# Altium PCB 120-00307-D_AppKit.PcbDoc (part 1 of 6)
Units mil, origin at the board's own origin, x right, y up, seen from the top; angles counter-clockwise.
Board outline 5150 x 3100 mil, 6 copper layers (L1, L2 (GND), L3-SIG, L4-SIG, L5 (PWR), L6), stack 61.956 mil thick; 413 components, 344 nets, 1685 pads, 1021 vias.
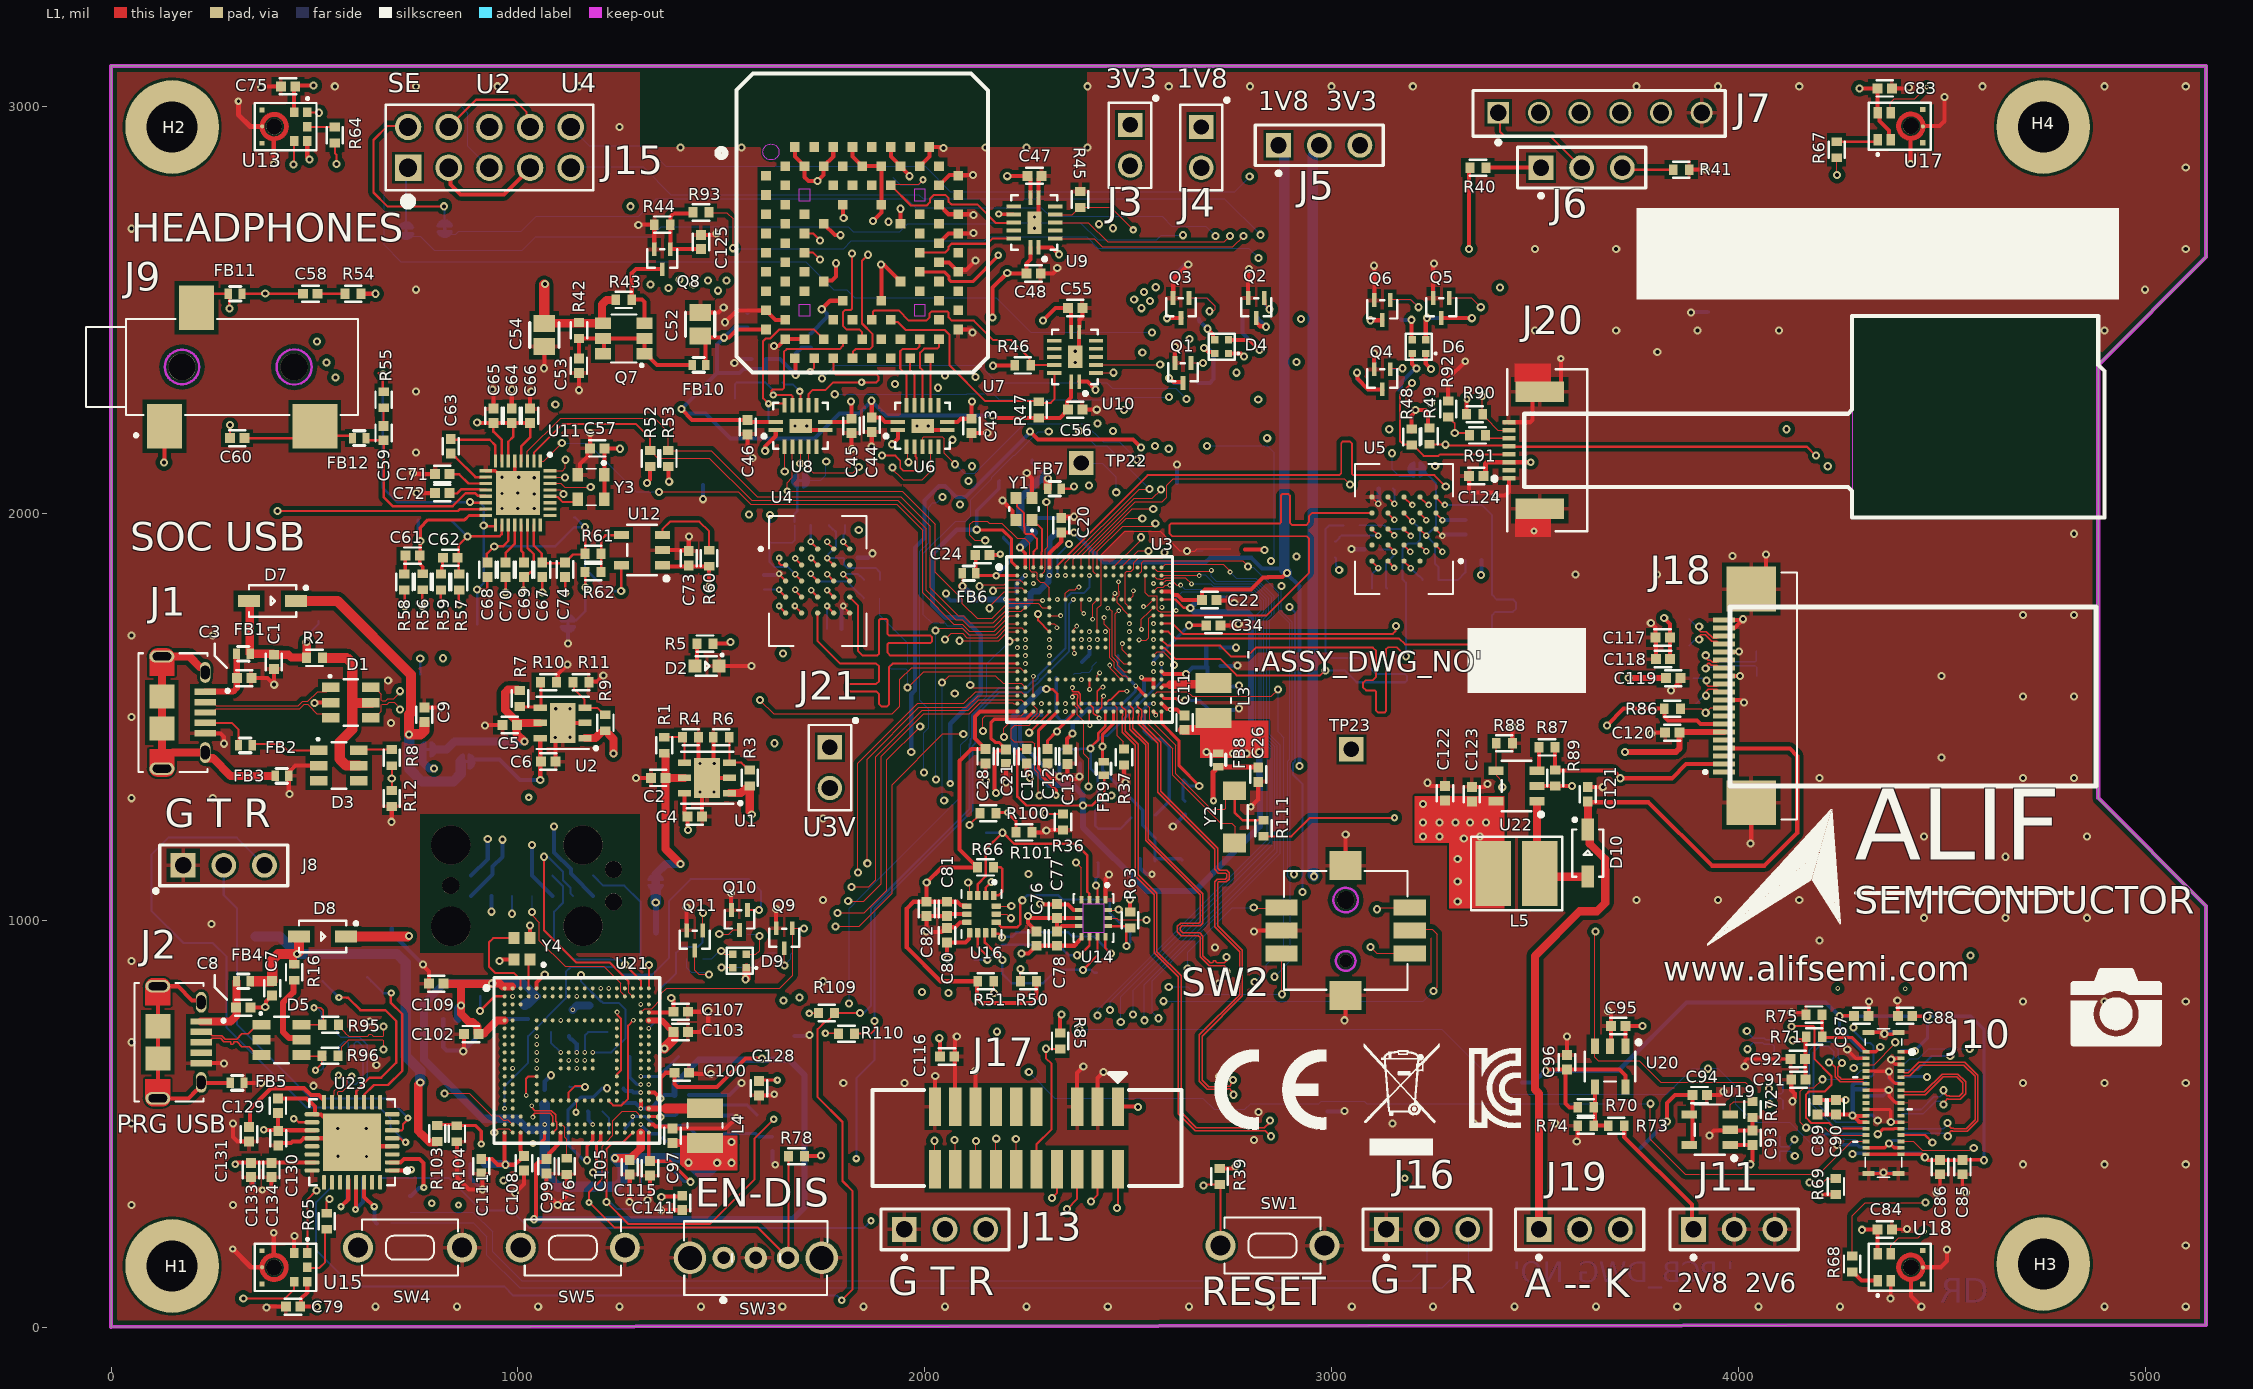
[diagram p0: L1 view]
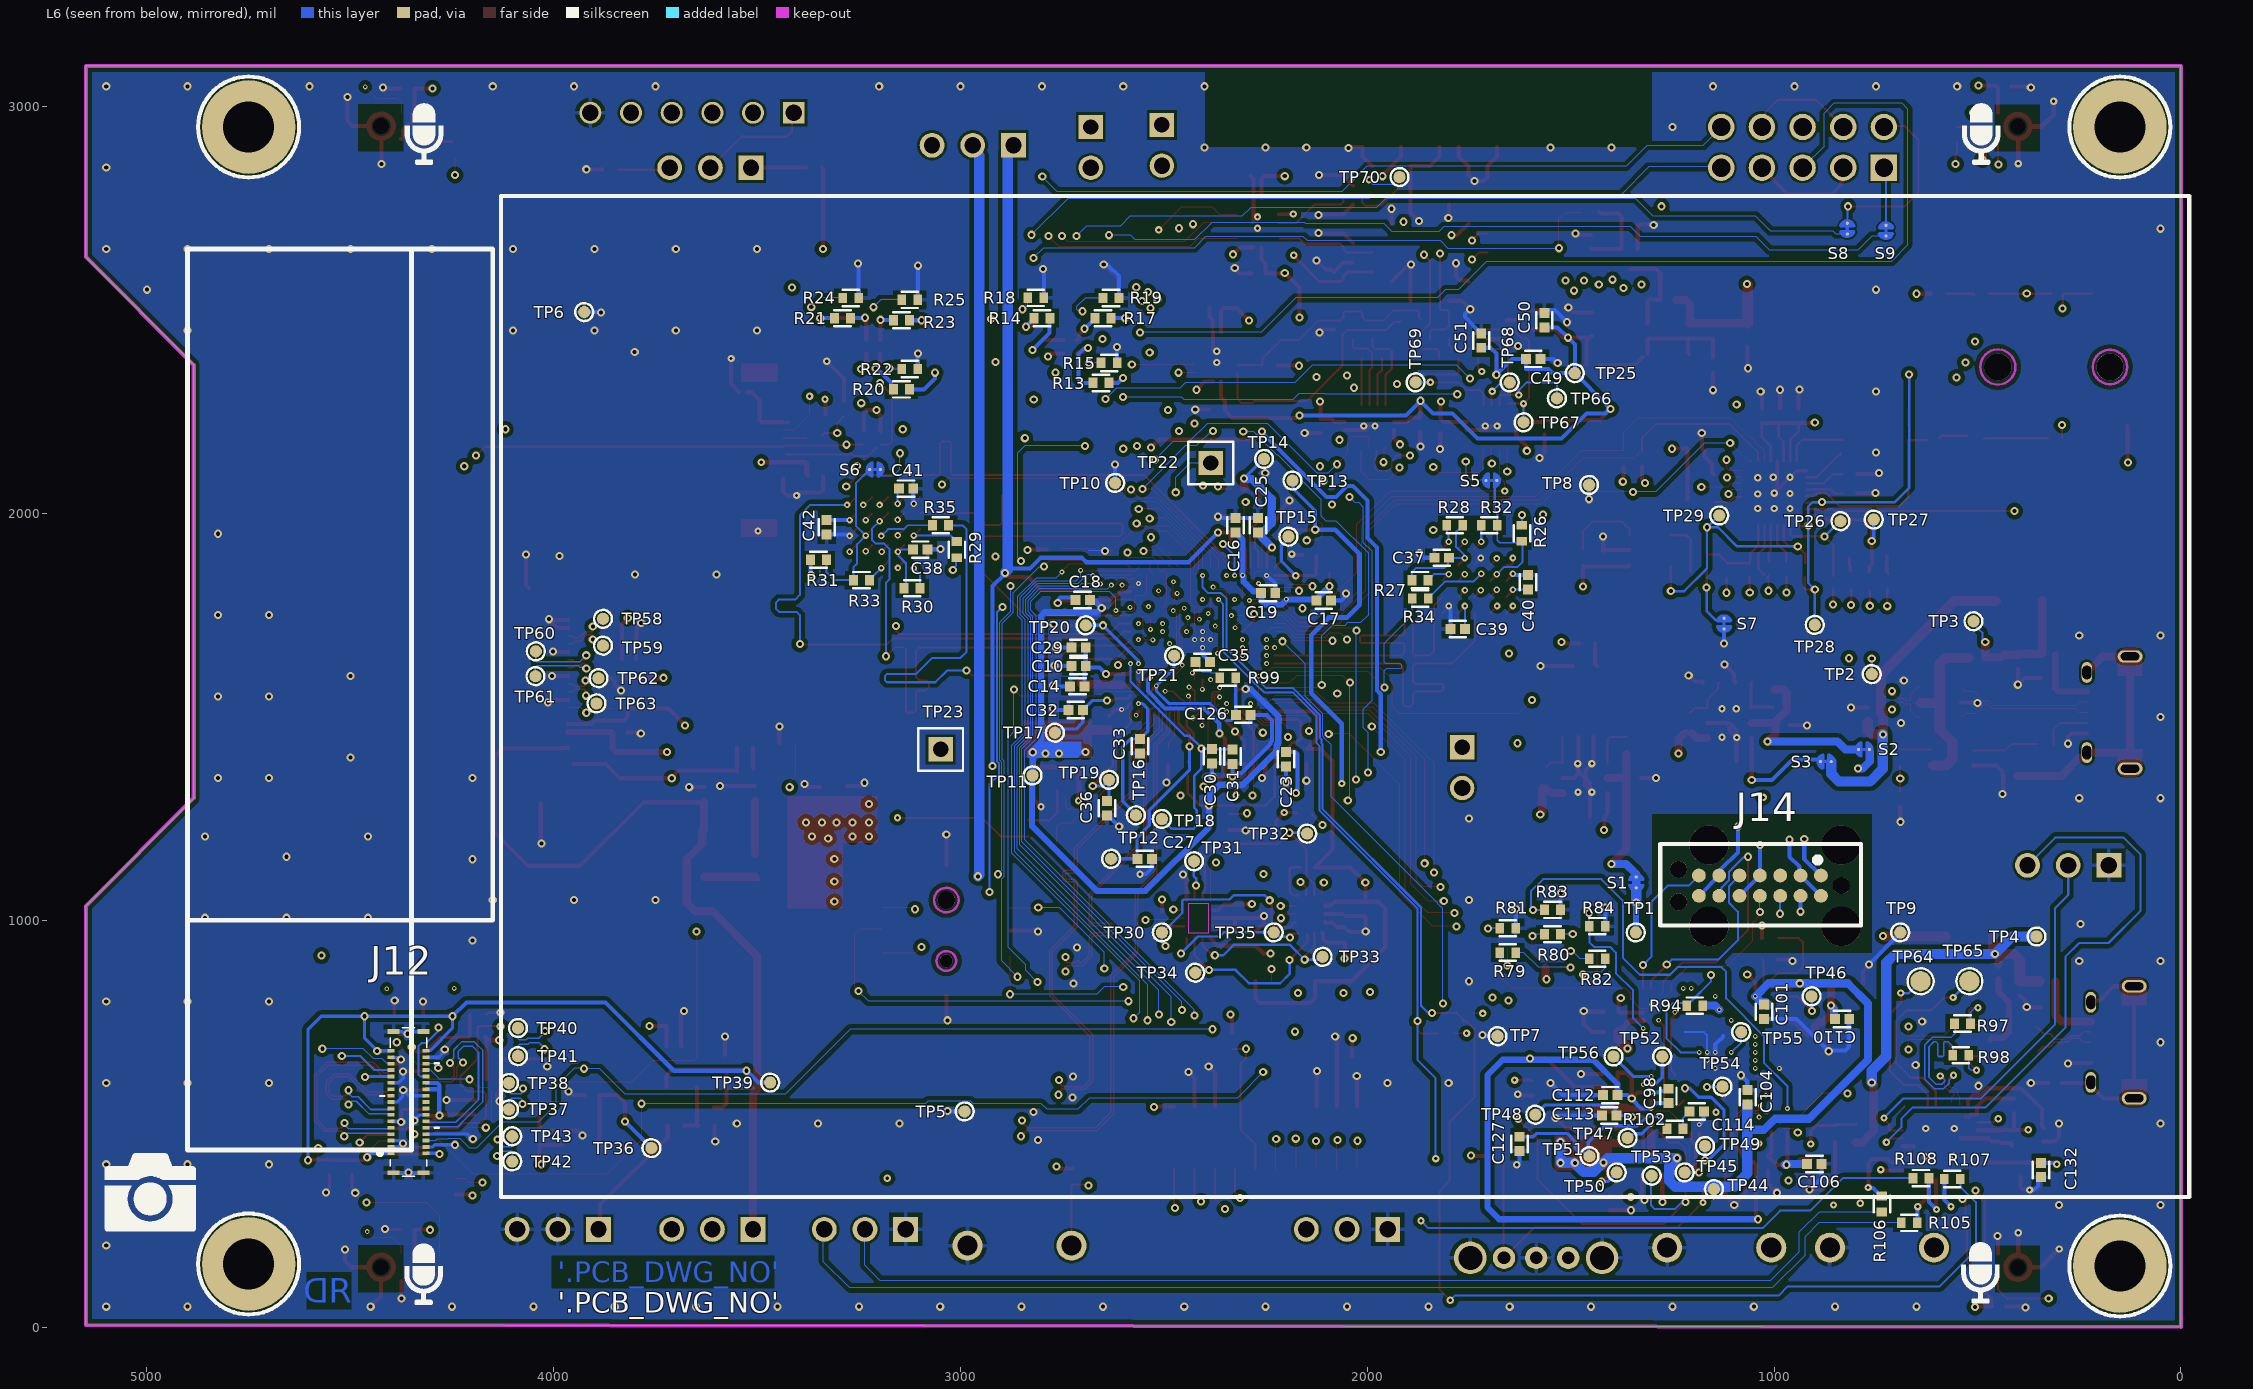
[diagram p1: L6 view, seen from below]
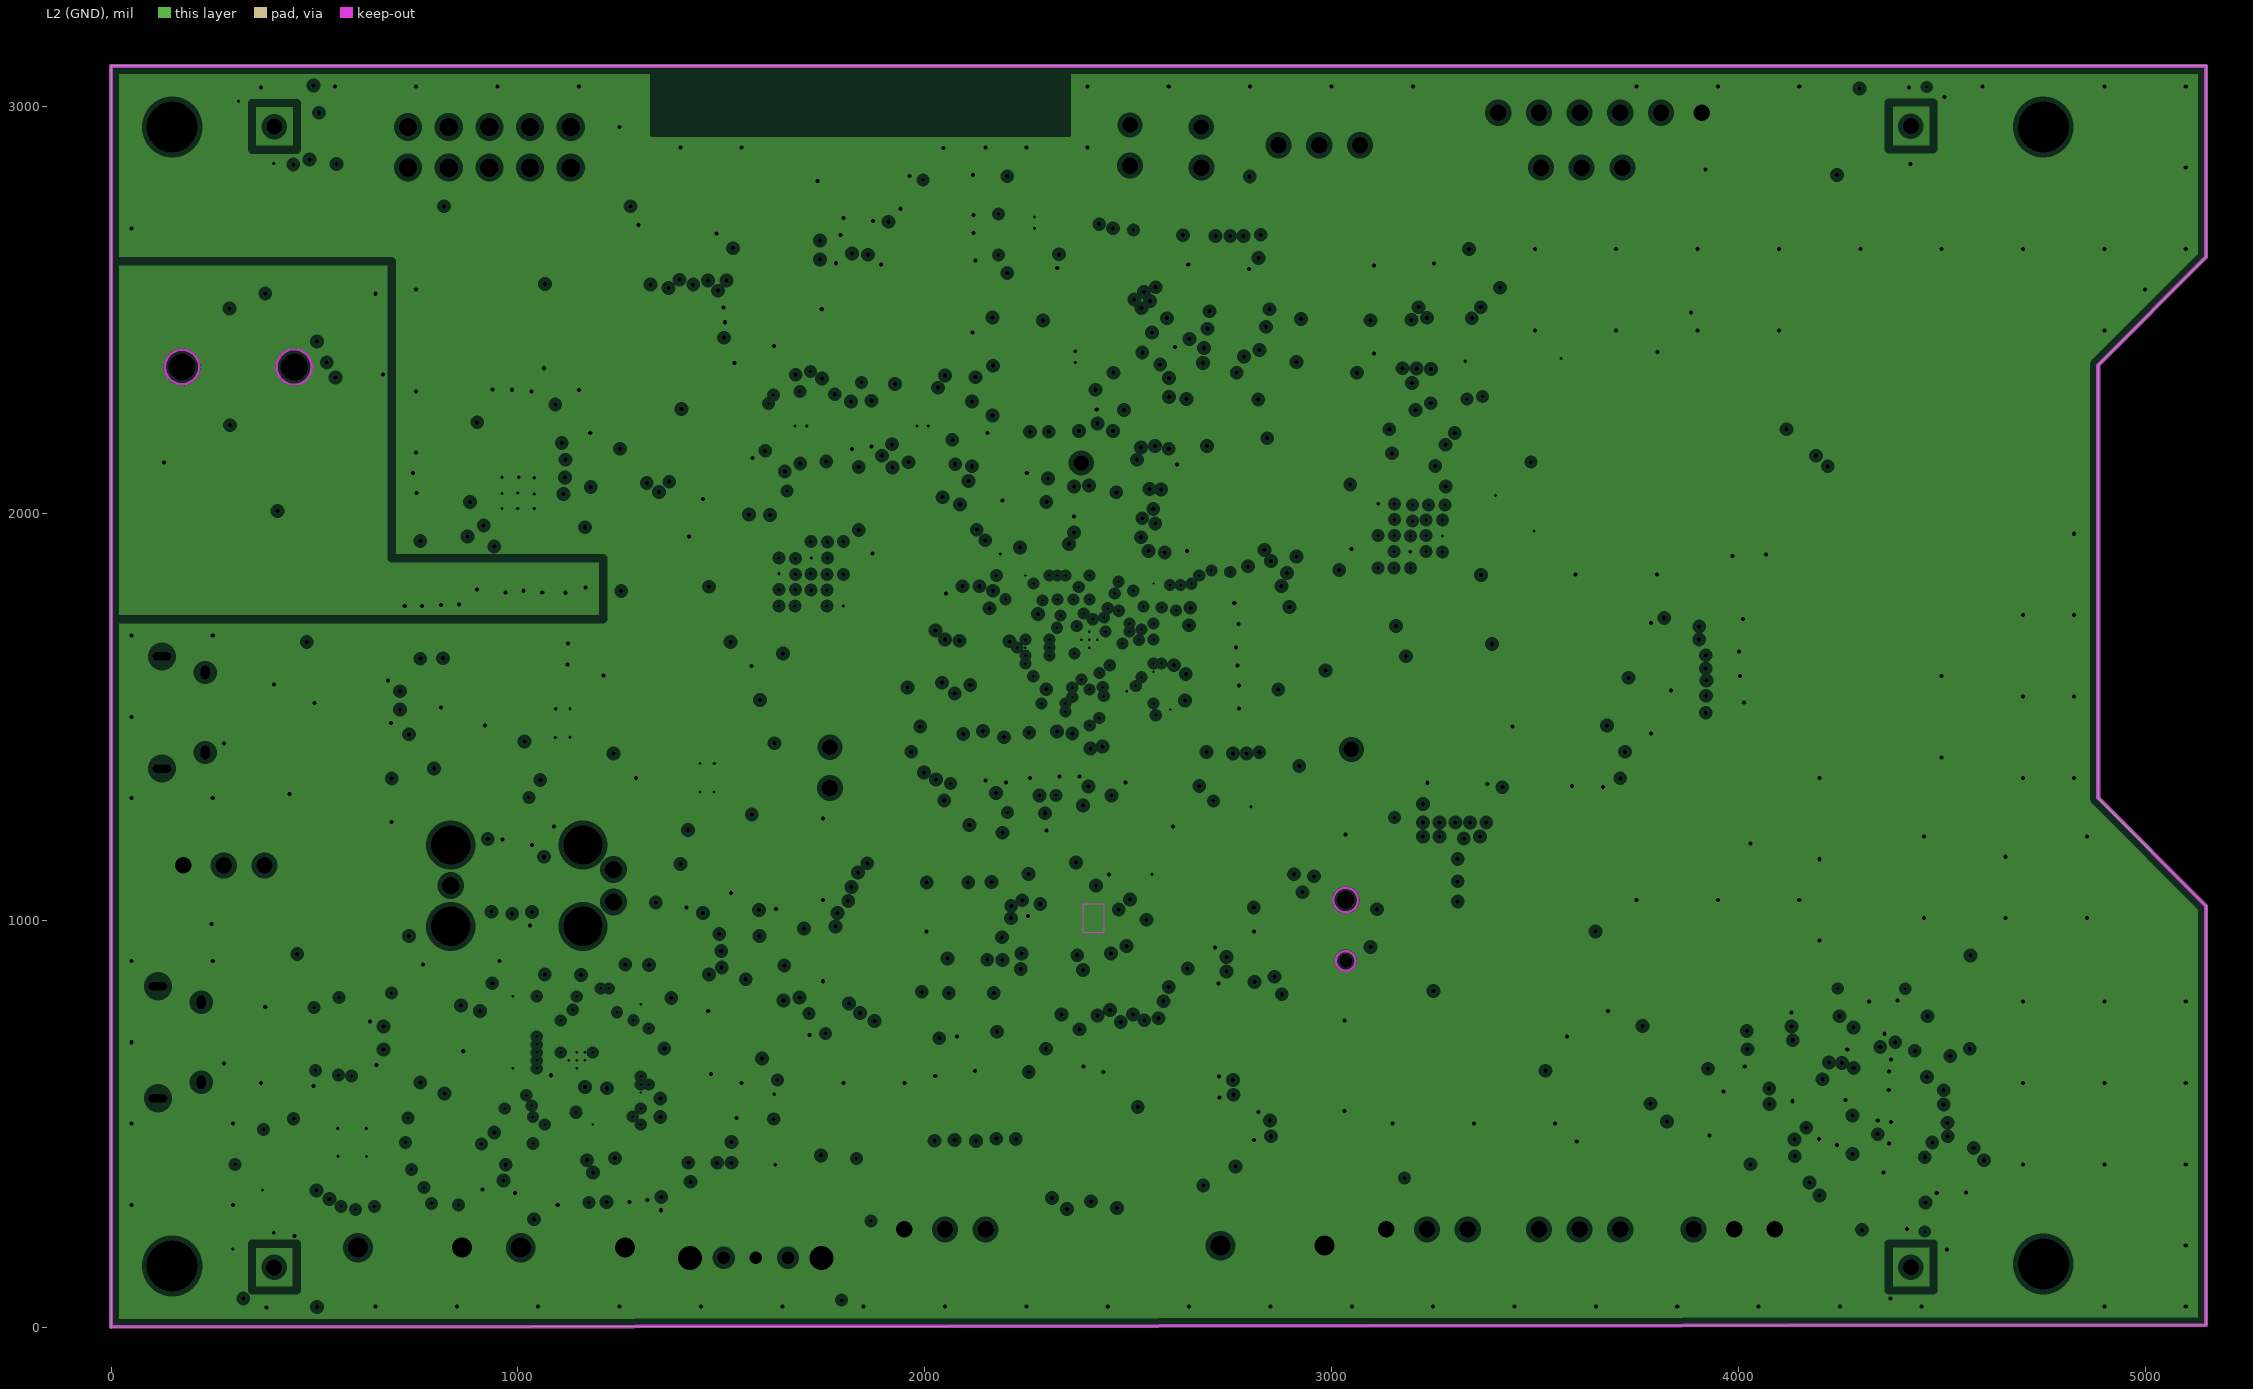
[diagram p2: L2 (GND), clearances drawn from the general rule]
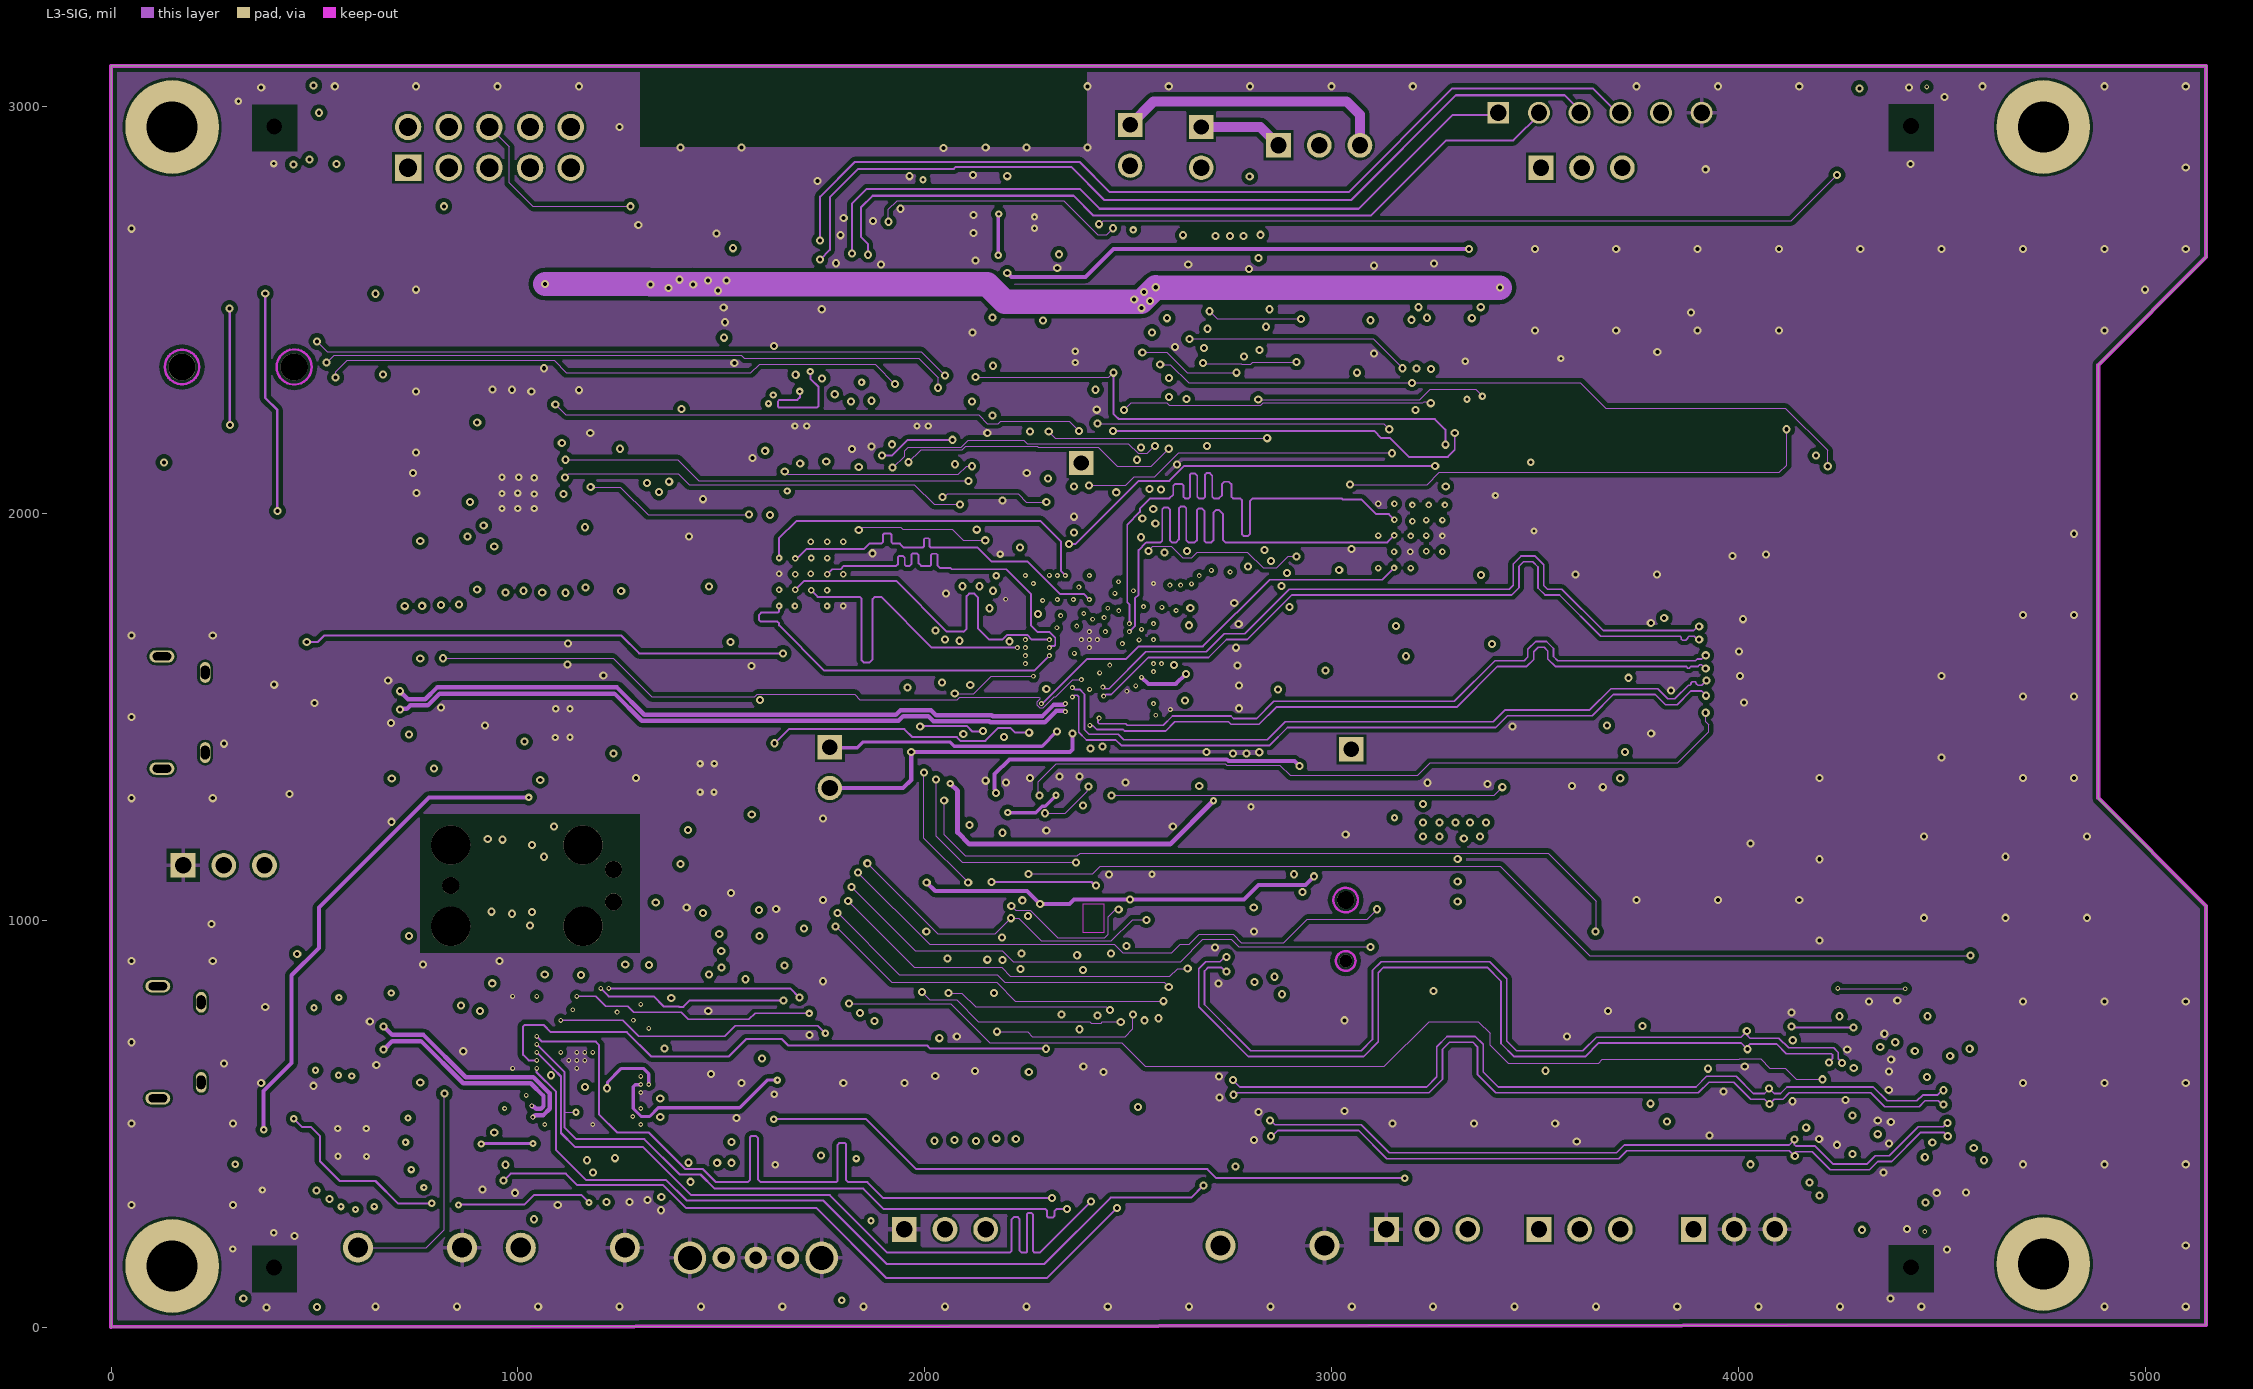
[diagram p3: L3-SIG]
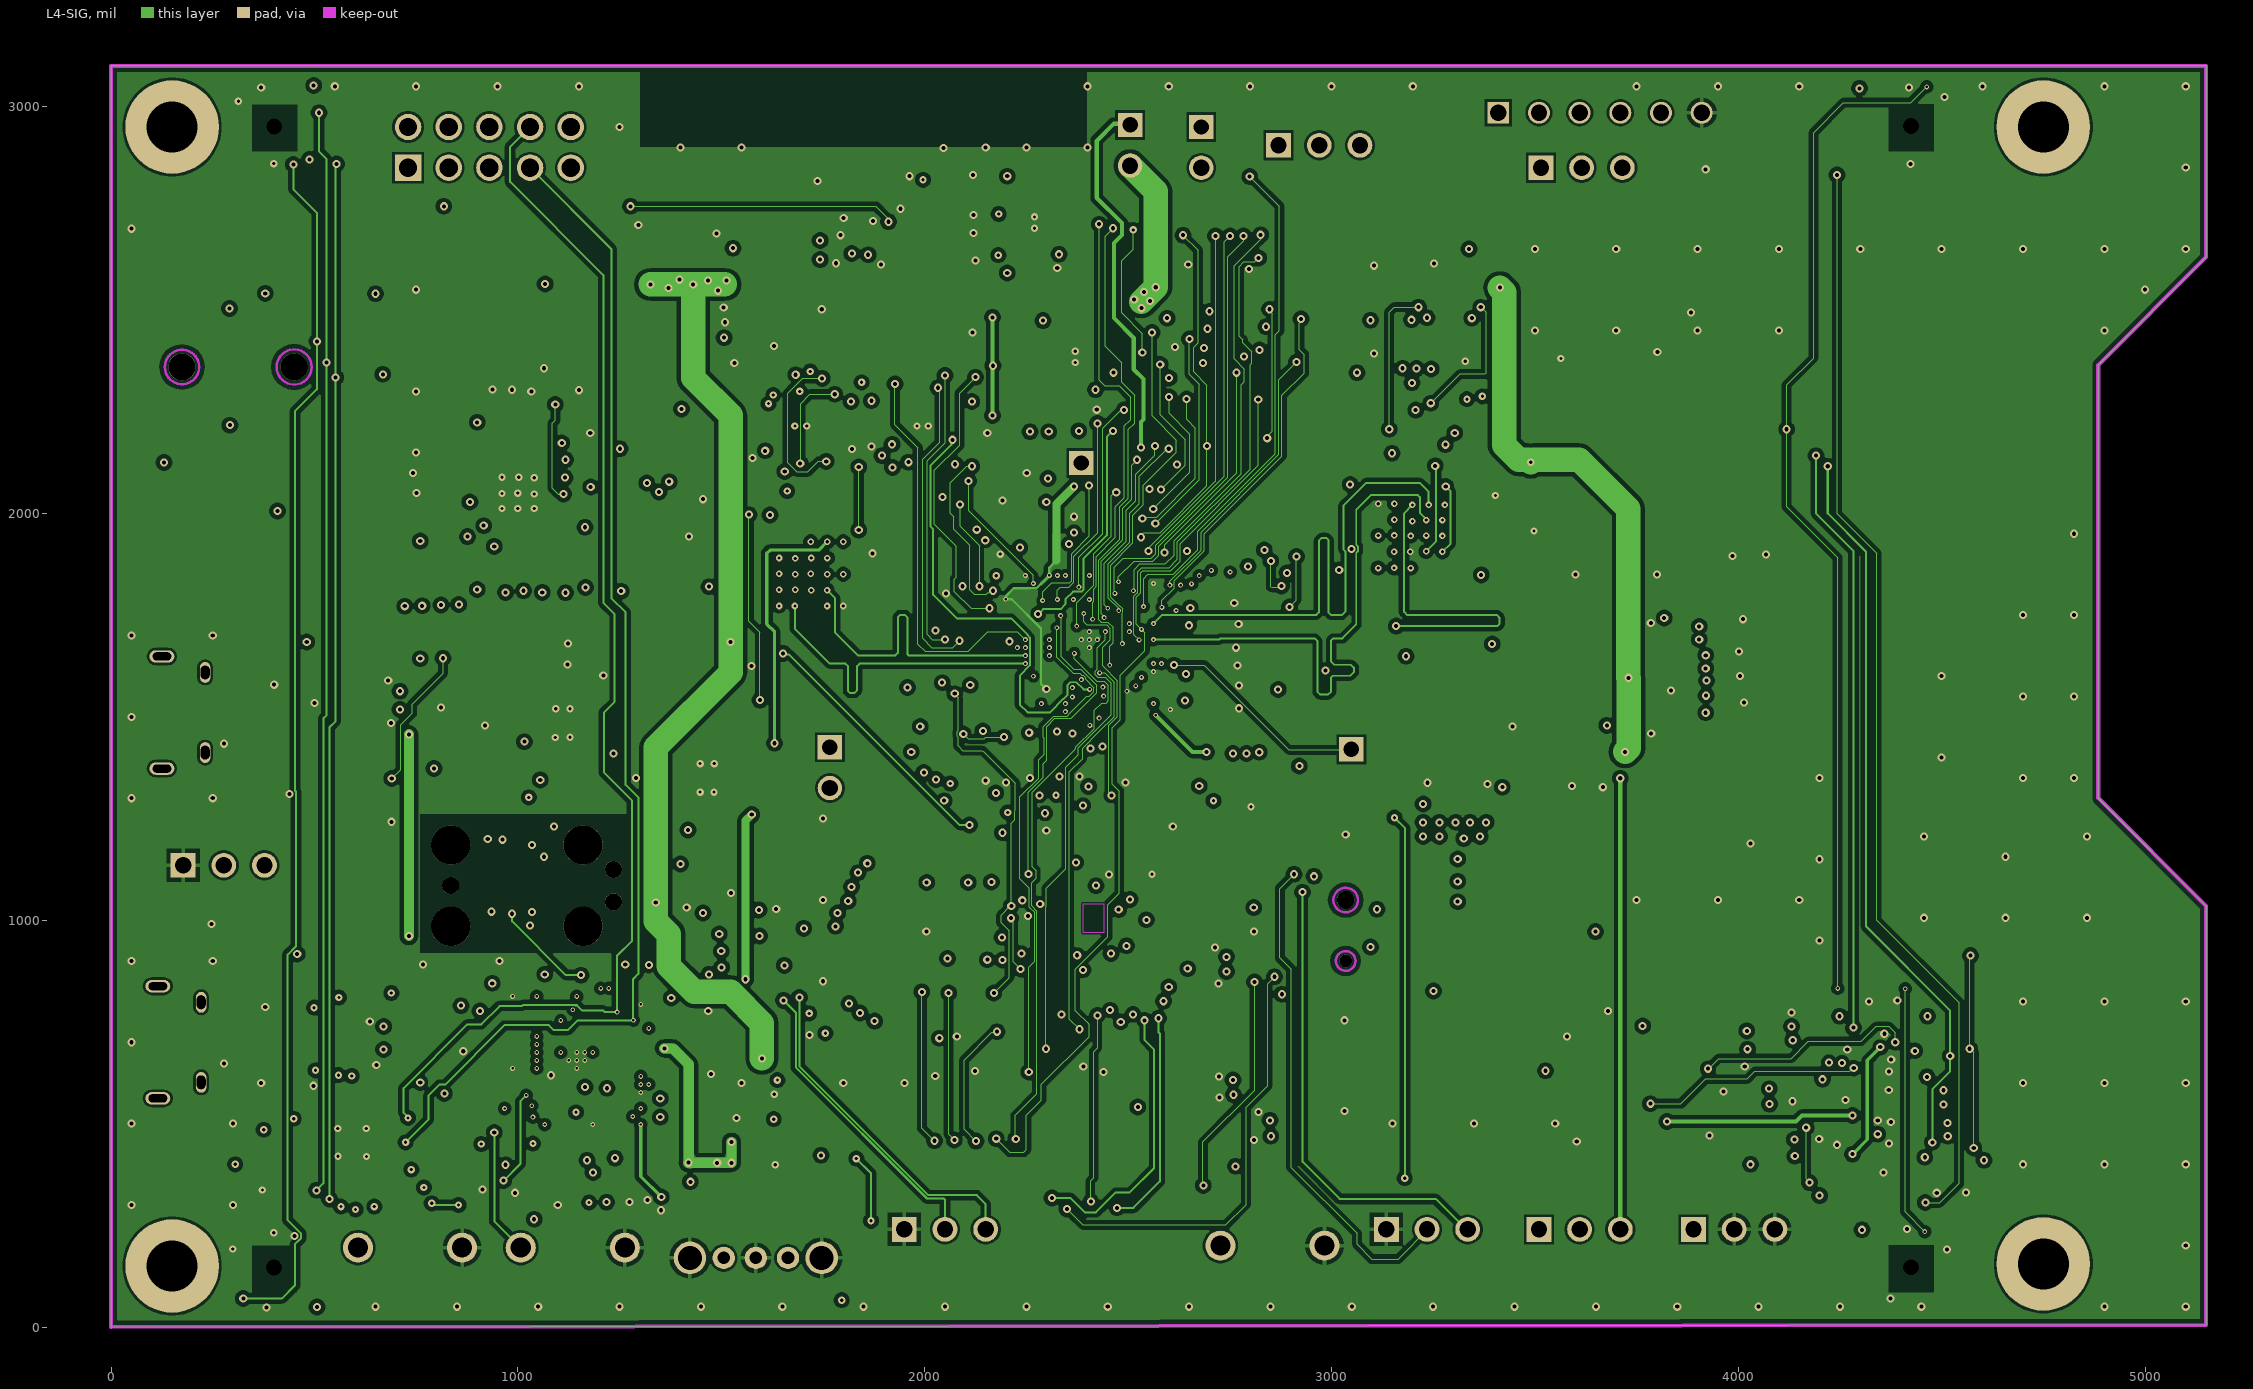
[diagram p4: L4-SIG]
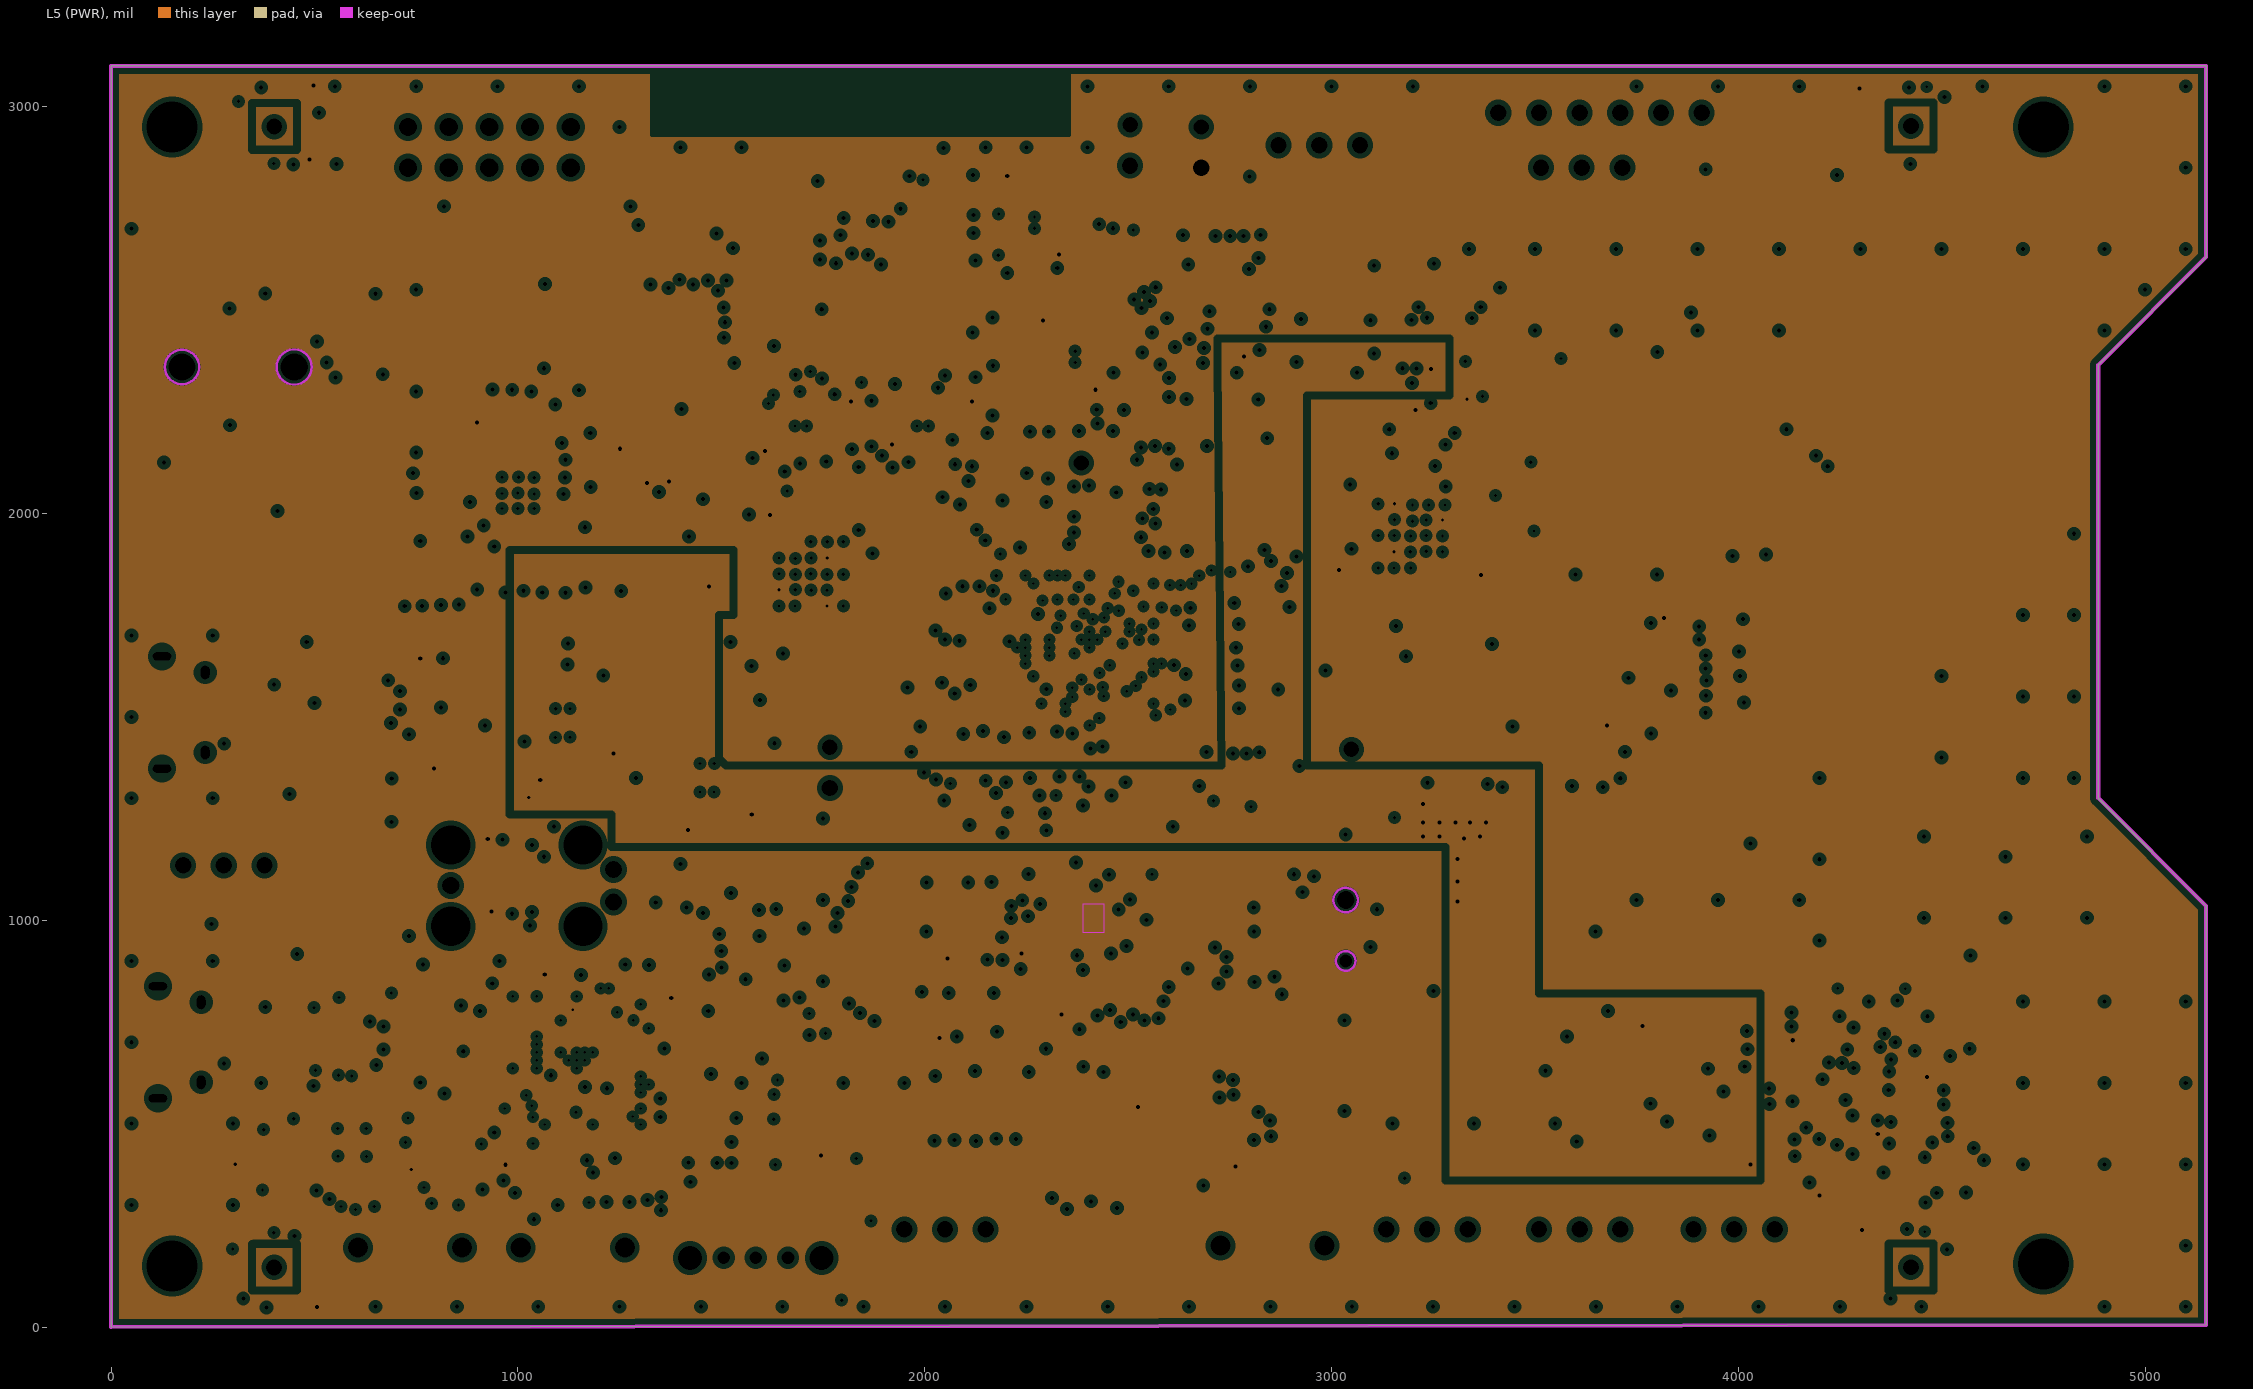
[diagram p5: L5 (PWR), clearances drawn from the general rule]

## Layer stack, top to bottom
Top Solder: solder mask 0.7, SM-001, Dk 4
L1: signal copper 1.378
Dielectric 1: prepreg 3.1, PP-008, Dk 4.1
L2 (GND): plane copper 0.6, net (Multiple Nets)
Dielectric 3: core 4.51, Core-035, Dk 4.7
L3-SIG: signal copper 0.6
Dielectric 2: prepreg 41.58, PP-006, Dk 4.1
L4-SIG: signal copper 0.6
Dielectric 6: core 4.51, Core-035, Dk 4.7
L5 (PWR): plane copper 0.6, net (Multiple Nets)
Dielectric 8: prepreg 3.1, PP-008, Dk 4.1
L6: signal copper 1.378
Bottom Solder: solder mask 0.7, SM-001, Dk 4

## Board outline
0,0 0,3100 5150,3100 5150,2630 4885,2365 4885,1300 5150,1035 5150,5

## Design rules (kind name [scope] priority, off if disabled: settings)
Clearance [All] p1: gap=5 ignorepadtopadclearanceinfootprint=TRUE except(0: Arc-Hole Track-Hole SMDPad-Hole THPad-Hole Via-Hole Fill-Hole Poly-Hole Region-Hole Text-Hole; 3: Arc-Arc Arc-Track Arc-SMDPad Track-Track Track-SMDPad Track-Via; 4: Arc-THPad Arc-Via Track-THPad SMDPad-SMDPad SMDPad-THPad SMDPad-Via THPad-THPad THPad-Via; 6: THPad-Poly; 10: Arc-Poly Track-Poly SMDPad-Poly Via-Poly Fill-Poly Poly-Poly)
DiffPairsRouting DiffPairsRouting-90 [All] p1: maxlimit=10 minlimit=4 mostfreqgap=10 toplayer_mingap=5 toplayer_maxgap=5 toplayer_prefgap=5 toplayer_minwidth=3 toplayer_maxwidth=3 toplayer_prefwidth=3 midlayer1_maxgap=4 midlayer1_prefgap=4 midlayer1_minwidth=11 midlayer1_maxwidth=11 midlayer1_prefwidth=11 midlayer2_mingap=10 midlayer2_minwidth=15 midlayer2_maxwidth=15 midlayer2_prefwidth=15 bottomlayer_mingap=10 bottomlayer_minwidth=15 bottomlayer_maxwidth=15 bottomlayer_prefwidth=15 maxuncoupledlength=500
DiffPairsRouting DiffPairsRouting_100 [All] p2: maxlimit=10 minlimit=3.8 mostfreqgap=10 toplayer_maxgap=3.8 toplayer_prefgap=3.8 toplayer_minwidth=3.2 toplayer_maxwidth=3.2 toplayer_prefwidth=3.2 midlayer1_mingap=10 midlayer1_minwidth=4.2 midlayer1_maxwidth=4.2 midlayer1_prefwidth=4.2 midlayer2_mingap=10 midlayer2_minwidth=4.2 midlayer2_maxwidth=4.2 midlayer2_prefwidth=4.2 bottomlayer_mingap=7 bottomlayer_maxgap=7 bottomlayer_prefgap=7 bottomlayer_minwidth=3.8 bottomlayer_maxwidth=3.8 bottomlayer_prefwidth=3.8 maxuncoupledlength=500
HoleSize [All] p1: absolutevalues=TRUE maxlimit=300 minlimit=1 maxpercent=80.000 minpercent=20.000
MinimumSolderMaskSliver [All] p1: minsoldermaskwidth=0
PlaneClearance [All] p1: clearance=12
PlaneConnect [All] p1: pad.planeconnectstyle=Relief pad.reliefexpansion=20 pad.reliefentries=4 pad.reliefconductorwidth=10 pad.reliefairgap=10 via.planeconnectstyle=Direct via.reliefexpansion=20 via.reliefentries=4 via.reliefconductorwidth=10 via.reliefairgap=10
PolygonConnect [All] p1: thpad.connectstyle=Relief thpad.reliefconductorwidth=10 thpad.reliefentries=4 thpad.polygonreliefangle="90 Angle" thpad.airgapwidth=10 smdpad.connectstyle=Relief smdpad.reliefconductorwidth=10 smdpad.reliefentries=4 smdpad.polygonreliefangle="90 Angle" smdpad.airgapwidth=10 via.connectstyle=Direct via.reliefconductorwidth=10 via.reliefentries=4 via.polygonreliefangle="90 Angle" via.airgapwidth=10
RoutingVias [All] p1: holewidth=8 width=18 viastyle="Through Hole" minholewidth=6 minwidth=12 maxholewidth=10 maxwidth=20
SilkToSilkClearance [All] p1: silktosilkclearance=3
SilkToSolderMaskClearance [IsPad] p1: minsilkscreentomaskgap=0 clearancetoexposedcopper=TRUE
SolderMaskExpansion [All] p1: expansion=4 istentingtop=FALSE
Width Width_1 [All] p1: maxlimit=100 minlimit=3 preferedwidth=6 minimp=50.000000 maximp=50.000000 favimp=50.000000
Width Single-ended [InNetClass('50-Ohm-Single')] p2: maxlimit=4.72 minlimit=4.72 preferedwidth=4.72 minimp=50.000000 maximp=50.000000 favimp=50.000000
23 further rules are at their usual default settings.

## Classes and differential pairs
differential pair class dIFF100: MIPI_CSI_0 MIPI_CSI_1 MIPI_CSI_C MIPI_DSI_0 MIPI_DSI_1 MIPI_DSI_C
differential pair class dIF90: USB_CYP USB_D USB_DEV USB_FTDI USB_U
net class 100: MIPI_CSI_0_N MIPI_CSI_0_P MIPI_CSI_1_N MIPI_CSI_1_P MIPI_CSI_C_N MIPI_CSI_C_P MIPI_DSI_0_N MIPI_DSI_0_P MIPI_DSI_1_N MIPI_DSI_1_P MIPI_DSI_C_N MIPI_DSI_C_P
net class 90: USB_CYP_N USB_CYP_P USB_D_N USB_D_P USB_DEV_N USB_DEV_P USB_FTDI_N USB_FTDI_P
component class 14-CypressSEUART: C129 C130 C131 C132 C133 C134 J8 R105 R106 R107 R108 TP64 TP65 U23
component class 13-JLINK_2: C116 D9 J14 J15 J16 J17 Q9 Q10 Q11 R79 R80 R81 R82 R83 R84 R85 R94 R109 R110 S8 S9 SH15A SH15B SW4 SW5
component class 12-JLINK_1: C97 C98 C99 C100 C101 C102 C103 C104 C105 C106 C107 C108 C109 C110 C111 C112 C113 C114 C115 C127 C128 C141 J13 L4 R76 R78 R102 R103 R104 R111 SW3 TP44 TP45 TP46 TP47 TP48 TP49 TP50 TP51 TP52 TP53 TP54 TP55 TP56 U21 Y4
component class 10-MIPI_DSI: C117 C118 C119 C120 C121 C122 C123 C124 D10 J18 J19 J20 L5 R86 R87 R88 R89 R90 R91 R92 TP58 TP59 TP60 TP61 TP62 TP63 U22
component class 9-MIPI_CSI: C85 C86 C87 C88 C89 C90 C91 C92 C93 C94 C95 C96 J10 J11 J12 R69 R70 R71 R72 R73 R74 R75 SH11 TP36 TP37 TP38 TP39 TP40 TP41 TP42 TP43 U19 U20
component class 8-Sensors: C75 C76 C77 C78 C79 C80 C81 C82 C83 C84 R63 R64 R65 R66 R67 R68 SW2 TP30 TP31 TP32 TP33 TP34 TP35 U13 U14 U15 U16 U17 U18
component class 7-CODEC: C57 C58 C59 C60 C61 C62 C63 C64 C65 C66 C67 C68 C69 C70 C71 C72 C73 C74 FB11 FB12 J9 R54 R55 R56 R57 R58 R59 R60 R61 R62 S7 TP26 TP27 TP28 TP29 U11 U12 Y3
component class 6-GPIOTranslate: R48 R49 R50 R51 R52 R53 S5 S6
component class 5-WiFi: C43 C44 C45 C46 C47 C48 C49 C50 C51 C52 C53 C54 C55 C56 C125 FB10 J6 J7 Q7 Q8 R40 R41 R42 R43 R44 R45 R46 R47 R93 SH6 TP25 TP66 TP67 TP68 TP69 TP70 U6 U7 U8 U9 U10
component class 4-CPUMipiXoMemory: C37 C38 C39 C40 C41 C42 R26 R27 R28 R29 R30 R31 R32 R33 R34 R35 R36 R37 R39 R100 R101 SW1 TP22 TP23 U4 U5 Y1 Y2
component class 3-CPUPower: C10 C11 C12 C13 C14 C15 C16 C17 C18 C19 C20 C21 C22 C23 C24 C25 C26 C27 C28 C29 C30 C31 C32 C33 C34 C35 C36 C126 FB6 FB7 FB8 FB9 J3 J4 J5 J21 L3 R99 SH3 SH4 SH5 TP11 TP12 TP13 TP14 TP15 TP16 TP17 TP18 TP19 TP20 TP21 U3
component class 2-PowerInput: C1 C2 C3 C4 C5 C6 C7 C8 C9 D1 D2 D3 D4 D5 D6 D7 D8 FB1 FB2 FB3 FB4 FB5 H1 H2 H3 H4 J1 J2 Q1 Q2 Q3 Q4 Q5 Q6 R1 R2 R3 R4 R5 R6 R7 R8 R9 R10 R11 R12 R13 R14 R15 R16 R17 R18 R19 R20 R21 R22 R23 R24 R25 R95 R96 R97 R98 S1 S2 S3 TP1 TP2 TP3 TP4 TP5 TP6 TP7 TP8 TP9 TP10 U1 U2
differential pair USB_CYP: +USB_CYP_P -USB_CYP_N
differential pair USB_U: +USB_U_P -USB_U_N
differential pair USB_FTDI: +USB_FTDI_P -USB_FTDI_N
differential pair USB_D: +USB_D_P -USB_D_N
differential pair USB_DEV: +USB_DEV_P -USB_DEV_N
differential pair MIPI_DSI_C: +MIPI_DSI_C_P -MIPI_DSI_C_N
differential pair MIPI_DSI_1: +MIPI_DSI_1_P -MIPI_DSI_1_N
differential pair MIPI_DSI_0: +MIPI_DSI_0_P -MIPI_DSI_0_N
differential pair MIPI_CSI_C: +MIPI_CSI_C_P -MIPI_CSI_C_N
differential pair MIPI_CSI_1: +MIPI_CSI_1_P -MIPI_CSI_1_N
differential pair MIPI_CSI_0: +MIPI_CSI_0_P -MIPI_CSI_0_N

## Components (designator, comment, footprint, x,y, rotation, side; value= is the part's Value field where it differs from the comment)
C1 "Cap" CAPC0402-01 400,1635 r270 top value=1.0u
C2 "Cap" CAPC0402-01 1345,1350 r0 top value=10u
C3 "Cap" CAPC0402-01 327.28,1595 r0 top value=10n
C4 "Cap_225M25VX5R0402_1" CAPC0402-01 1435,1255 r180 top value=2.2u
C5 "Cap" CAPC0402-01 980,1480 r0 top value=10u
C6 "Cap_225M25VX5R0402_1" CAPC0402-01 1075,1390 r180 top value=2.2u
C7 "Cap" CAPC0402-01 396,833 r270 top value=1.0u
C8 "Cap" CAPC0402-01 325,785 r0 top value=10n
C9 "Cap" CAPC0402-01 770,1505 r270 top locked value=100n
C10 "Cap" CAPC0402-01 2710,1625 r180 bottom value=100n
C11 "Cap_225M25VX5R0402_1" CAPC0402-01 2639,1486 r270 top value=2.2u
C12 "Cap" CAPC0402-01 2302,1403 r90 top value=1.0u
C13 "Cap" CAPC0402-01 2351,1402.28 r90 top value=1.0u
C14 "Cap" CAPC0402-01 2712.72,1575 r180 bottom value=10u
C15 "Cap" CAPC0402-01 2251,1403 r90 top value=100n
C16 "Cap" CAPC0402-01 2324,1970.81 r270 bottom value=100n
C17 "Cap" CAPC0402-01 2107,1786 r0 bottom value=100n
C18 "Cap" CAPC0402-01 2700,1787 r180 bottom value=100n
C19 "Cap" CAPC0402-01 2244,1804 r0 bottom value=100n
C20 "Cap" CAPC0402-01 2335.81,1970.81 r270 top value=100n
C21 "Cap" CAPC0402-01 2200,1402 r90 top value=100n
C22 "Cap" CAPC0402-01 2700,1787 r180 top value=100n
C23 "Cap" CAPC0402-01 2200,1396.09 r90 bottom value=100n
C24 "Cap" CAPC0402-01 2142,1898 r0 top value=100n
C25 "Cap" CAPC0402-01 2269,1970.81 r90 bottom value=100n
C26 "Cap" CAPC0402-01 2820,1358 r270 top value=100n
C27 "Cap" CAPC0402-01 2547,1151 r0 bottom value=100n
C28 "Cap" CAPC0402-01 2149.86,1402.86 r90 top value=100n
C29 "Cap" CAPC0402-01 2710,1670 r180 bottom value=1.0u
C30 "Cap" CAPC0402-01 2382,1403.28 r90 bottom value=1.0u
C31 "Cap" CAPC0402-01 2331.32,1402.28 r90 bottom value=100n
C32 "Cap" CAPC0402-01 2717,1517 r180 bottom value=1.0u
C33 "Cap" CAPC0402-01 2559,1428 r90 bottom value=1.0u
C34 "Cap" CAPC0402-01 2710,1725 r180 top value=1.0u
C35 "Cap" CAPC0402-01 2405,1635 r0 bottom value=1.0u
C36 "Cap" CAPC0402-01 2640,1275 r90 bottom value=1.0u
C37 "Cap" CAPC0402-01 1817.28,1891 r180 bottom value=100n
C38 "Cap" CAPC0402-01 3099,1911 r0 bottom value=100n
C39 "Cap" CAPC0402-01 1777.72,1716 r180 bottom value=100n
C40 "Cap" CAPC0402-01 1605,1831 r270 bottom value=100n
C41 "Cap" CAPC0402-01 3134,2061 r0 bottom value=100n
C42 "Cap" CAPC0402-01 3329,1966 r90 bottom value=100n
C43 "Cap" CAPC0402-01 2115,2215 r90 top value=100n
C44 "Cap" CAPC0402-01 1870,2217.72 r270 top value=100n
C45 "Cap" CAPC0402-01 1820,2215 r90 top value=100n
C46 "Cap" CAPC0402-01 1565,2212.28 r270 top value=100n
C47 "Cap" CAPC0402-01 2270,2830 r180 top value=100n
C48 "Cap" CAPC0402-01 2267.72,2590 r0 top value=100n
C49 "Cap" CAPC0402-01 1592.28,2380 r0 bottom value=10u
C50 "Cap" CAPC0402-01 1565,2475 r270 bottom value=100p
C51 "Cap" CAPC0402-01 1720,2425 r270 bottom value=100p
C52 "Cap" CAPC0805-01 1448,2465 r270 top value=100u
C53 "Cap" CAPC0402-01 1150,2362.72 r90 top value=100p
C54 "Cap" CAPC0805-01 1065,2438.57 r90 top value=100u
C55 "Cap" CAPC0402-01 2370,2505 r180 top value=100n
C56 "Cap" CAPC0402-01 2370,2255 r0 top value=100n
C57 "Cap" CAPC0402-01 1195,2160 r0 top value=100n
C58 "Cap" CAPC0402-01 490,2540 r0 top value=100n
C59 "Cap" CAPC0402-01 670,2197.72 r90 top value=100n
C60 "Cap" CAPC0402-01 310,2185 r180 top value=100p
C61 "Cap" CAPC0402-01 741,1896.31 r0 top value=100n
C62 "Cap" CAPC0402-01 833.72,1891 r0 top value=100n
C63 "Cap_225M25VX5R0402_1" CAPC0402-01 835,2165 r90 top value=2.2u
C64 "Cap" CAPC0402-01 985,2240 r270 top value=100n
C65 "Cap" CAPC0402-01 940,2240 r270 top value=100n
C66 "Cap" CAPC0402-01 1030,2240 r270 top value=4.7u
C67 "Cap" CAPC0402-01 1060,1861.31 r90 top value=100n
C68 "Cap" CAPC0402-01 925,1861.31 r90 top value=4.7u
C69 "Cap" CAPC0402-01 1015,1861.31 r90 top value=4.7u
C70 "Cap" CAPC0402-01 970,1861.31 r90 top value=4.7u
C71 "Cap_225M25VX5R0402_1" CAPC0402-01 814,2097 r0 top value=2.2u
C72 "Cap_225M25VX5R0402_1" CAPC0402-01 814,2050 r0 top value=2.2u
C73 "Cap" CAPC0402-01 1420,1890 r270 top value=1.0u
C74 "Cap" CAPC0402-01 1116,1862 r90 top value=10u
C75 "Cap" CAPC0402-01 435,3050 r180 top value=100n
C76 "Cap" CAPC0402-01 2275,955 r270 top value=10n
C77 "Cap" CAPC0402-01 2325,1022.72 r270 top value=100n
C78 "Cap_225M25VX5R0402_1" CAPC0402-01 2325,955 r270 top value=2.2u
C79 "Cap" CAPC0402-01 447.28,50 r180 top value=100n
C80 "Cap" CAPC0402-01 2055,962.72 r90 top value=100n
C81 "Cap" CAPC0402-01 2055,1027.72 r270 top value=100n
C82 "Cap" CAPC0402-01 2005,1027.72 r270 top value=100n
C83 "Cap" CAPC0402-01 4360,3045 r0 top value=100n
C84 "Cap" CAPC0402-01 4360,240 r0 top value=100n
C85 "Cap_225M25VX5R0402_1" CAPC0402-01 4551,393.28 r90 top value=2.2u
C86 "Cap_225M25VX5R0402_1" CAPC0402-01 4496,393.28 r90 top value=2.2u
C87 "Cap_225M25VX5R0402_1" CAPC0402-01 4302.72,765 r180 top value=2.2u
C88 "Cap" CAPC0402-01 4410,765 r0 top value=10u
C89 "Cap_225M25VX5R0402_1" CAPC0402-01 4195,540 r270 top value=2.2u
C90 "Cap" CAPC0402-01 4240,540 r270 top value=10u
C91 "Cap_225M25VX5R0402_1" CAPC0402-01 4148,608 r0 top value=2.2u
C92 "Cap" CAPC0402-01 4146.28,659 r0 top value=10u
C93 "Cap" CAPC0402-01 4035,465 r270 top value=1.0u
C94 "Cap" CAPC0402-01 3905,570 r180 top value=10u
C95 "Cap" CAPC0402-01 3705,740 r0 top value=1.0u
C96 "Cap" CAPC0402-01 3579,651 r270 top value=10u
C97 "Cap_225M25VX5R0402_1" CAPC0402-01 1380,470 r270 top value=2.2u
C98 "Cap" CAPC0402-01 1260,568 r270 bottom value=1.0u
C99 "Cap" CAPC0402-01 1070,395 r90 top value=1.0u
C100 "Cap" CAPC0402-01 1402.72,625 r180 top value=10u
C101 "Cap" CAPC0402-01 1025,775 r90 bottom value=100n
C102 "Cap" CAPC0402-01 885,720 r0 top value=100n
C103 "Cap" CAPC0402-01 1400,725 r180 top value=100n
C104 "Cap" CAPC0402-01 1065,565 r270 bottom value=100n
C105 "Cap" CAPC0402-01 1275,392.72 r90 top value=100n
C106 "Cap" CAPC0402-01 901,401 r0 bottom value=100n
C107 "Cap" CAPC0402-01 1400,775 r180 top value=100n
C108 "Cap" CAPC0402-01 1015,402.72 r90 top value=100n
C109 "Cap" CAPC0402-01 799,844 r180 top value=1.0u
C110 "Cap" CAPC0402-01 833,757 r180 bottom value=100n
C111 "Cap" CAPC0402-01 910,395 r90 top value=100n
C112 "Cap" CAPC0402-01 1402.72,570 r180 bottom value=1.0u
C113 "Cap" CAPC0402-01 1405,520 r180 bottom value=1.0u
C114 "Cap" CAPC0402-01 1190,530 r0 bottom value=1.0u
C115 "Cap" CAPC0402-01 1325,390 r90 top value=1.0u
C116 "Cap" CAPC0402-01 2055,665 r0 top value=100n
C117 "Cap" CAPC0402-01 3814,1695 r180 top value=10u
C118 "Cap" CAPC0402-01 3815,1642 r180 top value=100n
C119 "Cap" CAPC0402-01 3840,1595 r180 top locked value=10u
C120 "Cap" CAPC0402-01 3838,1461 r180 top value=100n
C121 "Cap_225M25VX5R0402_1" CAPC0402-01 3630,1310 r270 top value=2.2u
C122 "Cap_225M25VX5R0402_1" CAPC0402-01 3279,1312 r270 top value=2.2u
C123 "Cap" CAPC0402-01 3345,1310 r90 top value=100n
C124 "Cap_225M25VX5R0402_1" CAPC0402-01 3356,2092 r180 top value=2.2u
C125 "Cap" CAPC0402-01 1450,2667.28 r270 top value=100n
C126 "Cap" CAPC0402-01 2305,1505 r0 bottom value=100p
C127 "Cap" CAPC0402-01 1626,450 r90 bottom value=100p
C128 "Cap" CAPC0402-01 1593,587 r90 top value=1.0u
C129 "Cap" CAPC0402-01 410,544 r270 top value=100n
C130 "Cap" CAPC0402-01 411,464 r90 top value=4.7u
C131 "Cap" CAPC0402-01 339,473.72 r90 top value=1.0u
C132 "Cap" CAPC0402-01 344,386 r90 bottom value=4.7u
C133 "Cap" CAPC0402-01 344,386 r90 top value=100n
C134 "Cap" CAPC0402-01 394,386 r90 top value=100n
C141 "Cap" CAPC0402-01 1404,305 r90 top value=1.0u
D1 "TVS 5V 2pF" WE-TVS_SOT23-6L 589.21,1535 r270 top
D2 "D LED2" LED_0603-GRN_AK 1465,1625 r0 top value=GREEN
D3 "TVS 5V 2pF" WE-TVS_SOT23-6L 560,1380 r270 top
D4 "SML-LX0404SIUPGUSB" LED_SML-LX0404_LUM 2730,2410 r180 top
D5 "TVS 5V 2pF" WE-TVS_SOT23-6L 419,706 r270 top
D6 "SML-LX0404SIUPGUSB" LED_SML-LX0404_LUM 3215,2410 r180 top
D7 "D Schottky" SOD123F_NXP 397,1785 r180 top value="60V  2A"
D8 "D Schottky" SOD123F_NXP 520,960 r180 top value="60V  2A"
D9 "SML-LX0404SIUPGUSB" LED_SML-LX0404_LUM 1545,900 r180 top
D10 "D Schottky" SOD123F_NXP 3630,1165 r270 top value="60V  2A"
FB1 "Inductor" FB_0402 325,1655 r0 top value=WBC
FB2 "Inductor" FB_0402 330,1430 r0 top value=WBC
FB3 "Inductor" FB_0402 420,1355 r0 top value=WBC
FB4 "Inductor" FB_0402 325,850 r0 top value=WBC
FB5 "Inductor" FB_0402 310,600 r0 top value=WBC
FB6 "Inductor" FB_0402 2109,1853 r0 top locked value=WBC
FB7 "Inductor" FB_0402 2319,2060.81 r180 top value=WBC
FB8 "Inductor" FB_0402 2722,1394 r270 top value=WBC
FB9 "Inductor" FB_0402 2440,1373 r90 top value=WBC
FB10 "Inductor" FB_0402 1445,2365 r0 top value=WBC
FB11 "Inductor" FB_0402 305,2540 r180 top value=WBC
FB12 "Inductor" FB_0402 610,2185 r180 top value=WBC
H1 "HOLE_128" Hole_#4 150,150 r180 top
H2 "HOLE_128" Hole_#4 150,2950 r180 top
H3 "HOLE_128" Hole_#4 4750,155 r180 top
H4 "HOLE_128" Hole_#4 4750,2950 r180 top
J1 "Conn_USB_MicroB_Rt_Angle" AMPHENOL_10118194-0001LF 125,1510.63 r270 top value=MicroB_RA
J2 "Conn_USB_MicroB_Rt_Angle" AMPHENOL_10118194-0001LF 115,700 r270 top value=MicroB_RA
J3 "TSW-102-07-G-S" CONN_77311-146-02LF_AMP_HDR_1x2_2.5MM_STRT 2505,2955 r90 top
J4 "TSW-102-07-G-S" CONN_77311-146-02LF_AMP_HDR_1x2_2.5MM_STRT 2680,2950 r90 top
J5 "TSW-103-07-G-S" CONN_HDR_1X3_STRT_0.100 2870,2905 r0 top
J6 "TSW-103-07-G-S" CONN_HDR_1X3_STRT_0.100 3515,2850 r0 top
J7 "TSW-106-07-G-S" CONN_SAMTEC_TSW-106-07-G-S 3660,2985 r0 top
J8 "TSW-103-07-G-S" CONN_HDR_1X3_STRT_0.100_no3D 177,1135 r0 top
J9 "SJ-3523-SMT" CONN_CUI_SJ-3523-SMT-TR 174.41,2360 r0 top
J10 "BM20B(0.8)-34DS-0.4V(51)" CONN_FPC_BM20B0834DS04V51_W/MODULE 4357.09,550.75 r90 top locked
J11 "TSW-103-07-G-S" CONN_HDR_1X3_STRT_0.100 3890,240 r0 top
J12 "BM20B(0.8)-34DS-0.4V(51)" CONN_FPC_BM20B0834DS04V51_W/MODULE 4357.09,552.99 r270 bottom locked
J13 "TSW-103-07-G-S" CONN_HDR_1X3_STRT_0.100 1950,240 r0 top locked
J14 "PGMG_CONTACT,14P,TC2070-IDC_1" TC2070-IDC 1035,1085 r0 bottom value=PGM_ARRAY
J15 "TSW-105-07-G-D" CONN_TSW-105-07-G-D_SAI 730,2850 r0 top
J16 "TSW-103-07-G-S" CONN_HDR_1X3_STRT_0.100 3135,240 r0 top
J17 "Hdr_M_2X10_1M27_STRT_KEY_CORTEX_1" SAMTEC_FTSH-110-01-X-DV-007-K 2250,465 r180 top value=2x10M_1m27
J18 "SFV20R-2STBE1HLF" CONN_FPC_TOP-ENT_FRONT-SLIDE_0.50_20 3965,1551.42 r90 top locked
J19 "TSW-103-07-G-S" CONN_HDR_1X3_STRT_0.100 3510,240 r0 top
J20 "SFV8R-4STBE1HLF" CONN_FPC_TOP-ENT_FRONT-SLIDE_0.50_8 3530.7,2155.3 r90 top
J21 "TSW-102-07-G-S" CONN_77311-146-02LF_AMP_HDR_1x2_2.5MM_STRT 1767,1425 r90 top
L3 "Inductor" INDC2520X120N 2710,1540 r270 top value=2.2u
L4 "Inductor" INDC2520X120N 1460,495 r270 top value=2.2u
L5 "Inductor" IND_IFSC_1515AH_VIS-M 3455,1115 r0 top value=22u
Q1 "NMOS-2_SOT" SC75_SSM_TOS-L 2635,2345.43 r180 top value="20V  180mA  2.4Ohm"
Q2 "NMOS-2_SOT" SC75_SSM_TOS-L 2815,2505 r180 top value="20V  180mA  2.4Ohm"
Q3 "NMOS-2_SOT" SC75_SSM_TOS-L 2630,2505 r180 top value="20V  180mA  2.4Ohm"
Q4 "NMOS-2_SOT" SC75_SSM_TOS-L 3125,2330 r180 top value="20V  180mA  2.4Ohm"
Q5 "NMOS-2_SOT" SC75_SSM_TOS-L 3270,2505 r180 top value="20V  180mA  2.4Ohm"
Q6 "NMOS-2_SOT" SC75_SSM_TOS-L 3125,2500 r180 top value="20V  180mA  2.4Ohm"
Q7 "FDC638P" SSOT-6 1260.32,2430 r90 top
Q8 "NMOS-2_SOT" SC75_SSM_TOS-L 1355,2625 r180 top value="20V  180mA  2.4Ohm"
Q9 "NMOS-2_SOT" SC75_SSM_TOS-L 1654.68,955.43 r180 top value="20V  180mA  2.4Ohm"
Q10 "NMOS-2_SOT" SC75_SSM_TOS-L 1544.68,1000.43 r180 top value="20V  180mA  2.4Ohm"
Q11 "NMOS-2_SOT" SC75_SSM_TOS-L 1434.68,950.43 r180 top value="20V  180mA  2.4Ohm"
R1 "Res3" RESC0402-01 1360,1430.32 r270 top value=33K2
R2 "Res3" RESC0402-01 500,1645 r180 top value=0R0
R3 "Res3" RESC0402-01 1570,1350 r90 top value=10K0
R4 "Res3" RESC0402-01 1424.69,1450 r180 top value=20K0
R5 "Res3" RESC0402-01 1460,1680 r180 top value=1K82
R6 "Res3" RESC0402-01 1500,1450 r0 top value=100K
R7 "Res3" RESC0402-01 1005,1545 r90 top value=8K66
R8 "Res3" RESC0402-01 690,1399.69 r270 top value=20K0
R9 "Res3" RESC0402-01 1215,1485.31 r90 top value=10K0
R10 "Res3" RESC0402-01 1075,1585 r180 top value=20K0
R11 "Res3" RESC0402-01 1155,1585 r180 top value=100K
R12 "Res3" RESC0402-01 690,1299.37 r270 top value=10K0
R13 "Res3" RESC0402-01 2654.69,2320.85 r0 bottom value=681R
R14 "Res3" RESC0402-01 2799.69,2480 r0 bottom value=1K00
R15 "Res3" RESC0402-01 2634.69,2370 r0 bottom value=100K
R16 "Res3" RESC0402-01 450,872 r90 top value=0R0
R17 "Res3" RESC0402-01 2650,2480 r180 bottom value=1K00
R18 "Res3" RESC0402-01 2815,2530 r0 bottom value=100K
R19 "Res3" RESC0402-01 2630,2529.57 r0 bottom value=100K
R20 "Res3" RESC0402-01 3145.31,2305 r0 bottom value=681R
R21 "Res3" RESC0402-01 3290,2480 r0 bottom value=1K00
R22 "Res3" RESC0402-01 3125,2355 r0 bottom value=100K
R23 "Res3" RESC0402-01 3145,2475 r180 bottom value=1K00
R24 "Res3" RESC0402-01 3270,2529.57 r0 bottom value=100K
R25 "Res3" RESC0402-01 3125,2525 r0 bottom value=100K
R26 "Res3" RESC0402-01 1620,1951.32 r270 bottom value=10K0
R27 "Res3" RESC0402-01 1870.31,1836 r0 bottom value=100K
R28 "Res3" RESC0402-01 1785,1971 r180 bottom value=100K
R29 "Res3" RESC0402-01 3009,1911 r270 bottom value=100K
R30 "Res3" RESC0402-01 3119,1816 r0 bottom value=100K
R31 "Res3" RESC0402-01 3349,1886 r180 bottom value=10K0
R32 "Res3" RESC0402-01 1700.32,1971 r180 bottom value=0R0
R33 "Res3" RESC0402-01 3243.69,1836 r0 bottom value=0R0
R34 "Res3" RESC0402-01 1870,1791 r180 bottom value=0R0
R35 "Res3" RESC0402-01 3049,1971 r0 bottom value=0R0
R36 "Res3" RESC0402-01 2340,1241.31 r90 top value=200R
R37 "Res3" RESC0402-01 2490,1401 r270 top value=200R
R39 "Res3" RESC0402-01 2725,370 r90 top value=100K
R40 "Res3" RESC0402-01 3360,2850 r0 top value=100K
R41 "Res3" RESC0402-01 3860,2845 r180 top value=1K00
R42 "Res3" RESC0402-01 1150.32,2450 r270 top value=0R0
R43 "Res3" RESC0402-01 1260.32,2525 r180 top value=100K
R44 "Res3" RESC0402-01 1355,2710 r0 top value=100K
R45 "Res3" RESC0402-01 2382,2772 r90 top value=100K
R46 "Res3" RESC0402-01 2241,2364 r180 top value=4K75
R47 "Res3" RESC0402-01 2280,2254.69 r270 top value=4K75
R48 "Res3" RESC0402-01 3197,2188 r270 top value=1K82
R49 "Res3" RESC0402-01 3241,2190 r270 top value=1K82
R50 "Res3" RESC0402-01 2255,850 r180 top value=1K82
R51 "Res3" RESC0402-01 2150,850 r0 top value=1K82
R52 "Res3" RESC0402-01 1325,2135 r90 top value=1K82
R53 "Res3" RESC0402-01 1370,2135 r90 top value=1K82
R54 "Res3" RESC0402-01 595,2540 r180 top value=20R0
R55 "Res3" RESC0402-01 670,2279.69 r270 top value=20R0
R56 "Res3" RESC0402-01 766,1831.94 r270 top value=33K2
R57 "Res3" RESC0402-01 856,1831.31 r270 top value=33K2
R58 "Res3" RESC0402-01 721,1831.63 r270 top value=20R0
R59 "Res3" RESC0402-01 811,1831.31 r270 top value=20R0
R60 "Res3" RESC0402-01 1470,1890 r270 top value=100K
R61 "Res3" RESC0402-01 1185,1901 r0 top value=10K0
R62 "Res3" RESC0402-01 1185,1856 r180 top value=20K0
R63 "Res3" RESC0402-01 2505,1000.31 r90 top value=100K
R64 "Res3" RESC0402-01 550,2930 r270 top value=33R2
R65 "Res3" RESC0402-01 530,260 r90 top value=33R2
R66 "Res3" RESC0402-01 2149.69,1130 r180 top value=100K
R67 "Res3" RESC0402-01 4242,2894 r270 top value=33R2
R68 "Res3" RESC0402-01 4280,154.68 r90 top value=33R2
R69 "Res3" RESC0402-01 4240,345.31 r90 top value=10K0
R70 "Res3" RESC0402-01 3625.31,540 r0 top value=23K7
R71 "Res3" RESC0402-01 4187,714 r180 top value=10K0
R72 "Res3" RESC0402-01 4035,534.68 r90 top value=100K
R73 "Res3" RESC0402-01 3700,495 r180 top value=150K
R74 "Res3" RESC0402-01 3625,495 r180 top value=20K0
R75 "Res3" RESC0402-01 4186,768 r0 top value=0R0
R76 "Res3" RESC0402-01 1120,395 r90 top value=200R
R78 "Res3" RESC0402-01 1685,420 r0 top locked value=100K
R79 "Res3" RESC0402-01 1654.68,920.43 r180 bottom value=681R
R80 "Res3" RESC0402-01 1544.68,965.43 r180 bottom value=1K00
R81 "Res3" RESC0402-01 1654.68,980.43 r0 bottom value=100K
R82 "Res3" RESC0402-01 1435,905.43 r180 bottom value=1K00
R83 "Res3" RESC0402-01 1544.68,1025.43 r0 bottom value=100K
R84 "Res3" RESC0402-01 1434.68,985.43 r0 bottom value=100K
R85 "Res3" RESC0402-01 2333,703 r90 top value=100K
R86 "Res3" RESC0402-01 3838,1520 r0 top value=10K0
R87 "Res3" RESC0402-01 3529.69,1425 r180 top value=1K00
R88 "Res3" RESC0402-01 3425,1435 r180 top value=100K
R89 "Res3" RESC0402-01 3550,1349.68 r90 top value=7R50
R90 "Res3" RESC0402-01 3352,2244 r0 top value=10K0
R91 "Res3" RESC0402-01 3359,2192 r0 top value=4K75
R92 "Res3" RESC0402-01 3287,2257 r90 top value=4K75
R93 "Res3" RESC0402-01 1450,2740 r0 top value=10K0
R94 "Res3" RESC0402-01 1195,790 r180 bottom value=100K
R95 "Res3" RESC0402-01 539,743 r180 top value=0R0
R96 "Res3" RESC0402-01 538,667 r180 top value=0R0
R97 "Res3" RESC0402-01 537,746 r180 bottom value=0R0
R98 "Res3" RESC0402-01 541.32,668 r180 bottom locked value=0R0
R99 "Res3" RESC0402-01 2343,1596 r180 bottom value=4K75
R100 "Res3" RESC0402-01 2156,1263 r0 top value=20K0
R101 "Res3" RESC0402-01 2244,1216 r0 top value=10K0
R102 "Res3" RESC0402-01 1244,487 r0 bottom value=4K75
R103 "Res3" RESC0402-01 802,476 r90 top value=20K0
R104 "Res3" RESC0402-01 850,475 r270 top value=10K0
R105 "Res3" RESC0402-01 668,256 r180 bottom value=0R0
R106 "Res3" RESC0402-01 735,302.31 r90 bottom value=0R0
R107 "Res3" RESC0402-01 562,364 r0 bottom value=0R0
R108 "Res3" RESC0402-01 639,366 r180 bottom value=0R0
R109 "Res3" RESC0402-01 1759,772 r0 top value=0R0
R110 "Res3" RESC0402-01 1808,721 r0 top value=0R0
R111 "Res3" RESC0402-01 2833,1226 r90 top value=0R0
S1 "SolderJumperShorted_Small" Solderbridge_Shorted#1 1339,1093 r270 bottom net-tie
S2 "SolderJumperShorted_Small" Solderbridge_Shorted#2 779,1420 r180 bottom net-tie
S3 "SolderJumperShorted_Small" Solderbridge_Shorted#3 873,1390 r0 bottom net-tie
S5 "SolderJumperShorted_Small" Solderbridge_Shorted#4 1695,2081 r0 bottom net-tie
S6 "SolderJumperShorted_Small" Solderbridge_Shorted#4 3210,2108 r180 bottom net-tie
S7 "SolderJumperShorted_Small" Solderbridge_Shorted#5 1123,1729 r90 bottom net-tie
S8 "SolderJumperShorted_Small" Solderbridge_Shorted#6 820,2700 r270 bottom net-tie
S9 "SolderJumperShorted_Small" Solderbridge_Shorted#6 725,2695 r270 bottom net-tie
SW1 "SW-SPST" SW_1825966-TL1107-1 2855,200 r0 top value=TL1107
SW2 "JS1400BFQ_5SW" SW_JS1400BFQ 3035,974.8 r180 top locked
SW3 "SPDT" SW_SPDT_OS10201MSQN1 1585,170 r0 top value=SPDT-5Pin
SW4 "SW-SPST" SW_1825966-TL1107-1 735,195 r0 top value=TL1107
SW5 "SW-SPST" SW_1825966-TL1107-1 1135,195 r0 top value=TL1107
TP1 "TP_SMPAD" TP_30_RND 1340,970 r0 bottom
TP2 "TP_SMPAD" TP_30_RND 760,1605 r0 bottom
TP3 "TP_SMPAD" TP_30_RND 510,1735 r0 bottom
TP4 "TP_SMPAD" TP_30_RND 355,960 r0 bottom
TP5 "TP_SMPAD" TP_30_RND 2990,530 r0 bottom
TP6 "TP_SMPAD" TP_30_RND 3925,2495 r0 bottom
TP7 "TP_SMPAD" TP_30_RND 1680,715 r0 bottom
TP8 "TP_SMPAD" TP_30_RND 1455,2070 r0 bottom
TP9 "TP_SMPAD" TP_30_RND 690,970 r0 bottom
TP10 "TP_SMPAD" TP_30_RND 2620,2075 r0 bottom
TP11 "TP_SMPAD" TP_30_RND 2823,1356 r0 bottom
TP12 "TP_SMPAD" TP_30_RND 2630,1151 r0 bottom
TP13 "TP_SMPAD" TP_30_RND 2184,2080.81 r0 bottom
TP14 "TP_SMPAD" TP_30_RND 2254,2134 r0 bottom
TP15 "TP_SMPAD" TP_30_RND 2194,1943 r0 bottom
TP16 "TP_SMPAD" TP_30_RND 2569,1258 r0 bottom
TP17 "TP_SMPAD" TP_30_RND 2768,1461 r0 bottom
TP18 "TP_SMPAD" TP_30_RND 2505,1249 r0 bottom
TP19 "TP_SMPAD" TP_30_RND 2635,1345 r0 bottom
TP20 "TP_SMPAD" TP_30_RND 2692.28,1725 r0 bottom
TP21 "TP_SMPAD" TP_30_RND 2475,1650 r0 bottom
TP22 "TSW-101-07-G-S" CONN_77311-146-01LF_AMP_HDR_1X1_2.5MM_STRT_No3D 2385,2124 r0 bottom
TP23 "TSW-101-07-G-S" CONN_77311-146-01LF_AMP_HDR_1X1_2.5MM_STRT_No3D 3049,1420 r0 bottom
TP25 "TP_SMPAD" TP_30_RND 1490,2345 r0 bottom
TP26 "TP_SMPAD" TP_30_RND 837,1981 r270 bottom
TP27 "TP_SMPAD" TP_30_RND 755,1985 r90 bottom
TP28 "TP_SMPAD" TP_30_RND 900,1726 r90 bottom
TP29 "TP_SMPAD" TP_30_RND 1135,1995 r0 bottom
TP30 "TP_SMPAD" TP_30_RND 2505,970 r0 bottom
TP31 "TP_SMPAD" TP_30_RND 2426,1145 r0 bottom
TP32 "TP_SMPAD" TP_30_RND 2148,1213 r0 bottom
TP33 "TP_SMPAD" TP_30_RND 2110,910 r0 bottom
TP34 "TP_SMPAD" TP_30_RND 2423,871 r0 bottom
TP35 "TP_SMPAD" TP_30_RND 2230,970 r0 bottom
TP36 "TP_SMPAD" TP_30_RND 3760,440 r0 bottom
TP37 "TP_SMPAD" TP_30_RND 4110,535 r0 bottom
TP38 "TP_SMPAD" TP_30_RND 4110,600 r0 bottom
TP39 "TP_SMPAD" TP_30_RND 3468,601 r0 bottom
TP40 "TP_SMPAD" TP_30_RND 4088,735 r0 bottom
TP41 "TP_SMPAD" TP_30_RND 4088,666 r0 bottom
TP42 "TP_SMPAD" TP_30_RND 4102,407 r0 bottom
TP43 "TP_SMPAD" TP_30_RND 4102,469 r0 bottom
TP44 "TP_SMPAD" TP_30_RND 1148,339 r0 bottom
TP45 "TP_SMPAD" TP_30_RND 1220,380 r0 bottom
TP46 "TP_SMPAD" TP_30_RND 908,813 r0 bottom
TP47 "TP_SMPAD" TP_30_RND 1360.32,465 r0 bottom
TP48 "TP_SMPAD" TP_30_RND 1587,522 r0 bottom
TP49 "TP_SMPAD" TP_30_RND 1170,445 r0 bottom
TP50 "TP_SMPAD" TP_30_RND 1387,380 r0 bottom
TP51 "TP_SMPAD" TP_30_RND 1454,420 r0 bottom
TP52 "TP_SMPAD" TP_30_RND 1275,665 r0 bottom
TP53 "TP_SMPAD" TP_30_RND 1301,372 r0 bottom
TP54 "TP_SMPAD" TP_30_RND 1127,591 r0 bottom
TP55 "TP_SMPAD" TP_30_RND 1081,725 r0 bottom
TP56 "TP_SMPAD" TP_30_RND 1395,665 r0 bottom
TP58 "TP_SMPAD" TP_30_RND 3879,1741 r90 bottom
TP59 "TP_SMPAD" TP_30_RND 3879,1675 r90 bottom
TP60 "TP_SMPAD" TP_30_RND 4044,1661 r90 bottom
TP61 "TP_SMPAD" TP_30_RND 4045,1600 r90 bottom
TP62 "TP_SMPAD" TP_30_RND 3890,1595 r90 bottom
TP63 "TP_SMPAD" TP_30_RND 3895,1533 r90 bottom
TP64 "TP_SMPAD" TP_50_RND 640,850 r180 bottom
TP65 "TP_SMPAD" TP_50_RND 520,850 r180 bottom
TP66 "TP_SMPAD" TP_30_RND 1534,2283 r90 bottom
TP67 "TP_SMPAD" TP_30_RND 1616,2224 r90 bottom
TP68 "TP_SMPAD" TP_30_RND 1650,2322 r0 bottom
TP69 "TP_SMPAD" TP_30_RND 1881.35,2322.35 r0 bottom
TP70 "TP_SMPAD" TP_30_RND 1921,2827 r0 bottom
U1 "NCP692MNADJT2G" DFN6_3X3_ONS 1465,1350 r180 top
U2 "NCP692MNADJT2G" DFN6_3X3_ONS 1110,1485 r180 top
U3 "Alif_E _Series_BGA194" "BGA194 _CENTERED" 2405.03,1689.97 r0 top locked
U4 "IC_OctalSPI_Generic_1" BGA24C100P5X5_800X600X100N 1737.03,1833.97 r0 top locked
U5 "IC_OctalSPI_Generic_1" BGA24C100P5X5_800X600X100N 3178.37,1961.63 r180 top
U6 "NTB0104BQ" DHVQFN-14(2.5x3.0)_NXP 1995,2215 r0 top
U7 "WE310F5-I" MODULE_TELIT_WE310F5-I_ME310G1 1846.22,2641.02 r0 top locked
U8 "NTB0104BQ" DHVQFN-14(2.5x3.0)_NXP 1695,2215 r0 top
U9 "NTB0104BQ" DHVQFN-14(2.5x3.0)_NXP 2270,2715 r90 top
U10 "NTS0104BQ" DHVQFN-14(2.5x3.0)_NXP 2370,2385 r90 top
U11 "WM8904CGEFL_V" QFN40P400X400X80-33N 1000,2050 r270 top
U12 "NCV8164ASNADJT1G" TSOT23-5_ONS 1305,1910 r180 top
U13 "T5848" MIC_T5848#1 401,2951 r180 top
U14 "ICM-42670-P_1" IC_ICM-42670-P 2415,1005 r270 top value=Gyro_Accel
U15 "T5848" MIC_T5848#2 400.71,146.57 r180 top
U16 "BMI323" PQFN50P250X300X88-14N 2140,1015 r270 top
U17 "T5838" MIC_T5838 4424.29,2951.99 r0 top value="PDM Mic"
U18 "T5838" MIC_T5838 4424.29,147.01 r0 top value="PDM Mic"
U19 "NCV8164ASNADJT1G" TSOT23-5_ONS 3930,485 r180 top
U20 "NCV8164ASNADJT1G" TSOT23-5_ONS 3685,640 r270 top
U21 "Alif_E _Series_BGA194" "BGA194 _CENTERED" 1144.72,655.28 r0 top locked
U22 "CAT4139TD-GT3" TSOT23-5_ONS 3455,1330 r180 top
U23 "CY7C65215A-32LTXI" QFN32_5x5x1-0p5_INF-M 592.43,454.16 r180 top
Y1 "Xtal_38M4_20PPM6PF_2016-4P_1" OSC_4p_2016_XRCGB38M400F2P00R0 2244,2010.81 r180 top value=38M400
Y2 "Xtal_32K768_20PPM6PF_3215-2P_1" XTAL_ABS07_ABR-M 2762,1254 r270 top value=32K768
Y3 "XO_12M288" OSC_4P_3225_1210_uChip_DSC1001DL5 1180,2065 r270 top value=12M288
Y4 "Xtal_38M4_20PPM6PF_2016-4P_1" OSC_4p_2016_XRCGB38M400F2P00R0 1010,930 r180 top value=38M400

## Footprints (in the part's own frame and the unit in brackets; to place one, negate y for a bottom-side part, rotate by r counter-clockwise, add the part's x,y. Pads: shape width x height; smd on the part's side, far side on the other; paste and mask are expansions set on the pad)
AMPHENOL_10118194-0001LF [mm]
  rect 0.4x1.35 smd: 1(-1.3,2.7) 2(-0.65,2.7) 3(0,2.7) 4(0.65,2.7) 5(1.3,2.7)
  oval 1.3x0.65 hole 0.55 slot 0.85 at 0 deg: S1(-2.5,2.7) S2(2.5,2.7)
  oval 0.775x1.55 hole 0.5 slot 1.15 at 90 deg: S3(-3.5,0) S6(3.5,0)
  rect 1.5x1.55 smd: S4(-1,0) S5(1,0)
  L1 region: 193 vertices and 0 holes, not listed, extent 2.3,-0.78 4,0.775
  L1 region: 193 vertices and 0 holes, not listed, extent -4,-0.775 -2.3,0.78
  silkscreen extent -3.7,-1.45 3.7,4.2, body extent -4.02,-2.65 4.03,2.88, height 2.74
BGA24C100P5X5_800X600X100N [mm]
  round 0.33 smd: A2(-1,2) A3(0,2) A4(1,2) A5(2,2) B1(-2,1) B2(-1,1) B3(0,1) B4(1,1) B5(2,1) C1(-2,0) C2(-1,0) C3(0,0) C4(1,0) C5(2,0) D1(-2,-1) D2(-1,-1) D3(0,-1) D4(1,-1) D5(2,-1) E1(-2,-2) E2(-1,-2) E3(0,-2) E4(1,-2) E5(2,-2)
  silkscreen extent -3.65,-4.05 3.05,4.05, body extent -3,-4 3,4, height 1
"BGA194 _CENTERED" [mm]
  round 0.25 smd: A1(-4.501,4.501) A2(-4.001,4.501) A3(-3.501,4.501) A4(-3.001,4.501) A5(-2.501,4.501) A6(-2.001,4.501) A7(-1.501,4.501) A8(-1.001,4.501) A9(-0.501,4.501) A10(-0.001,4.501) A11(0.499,4.501) A12(0.999,4.501) A13(1.499,4.501) A14(1.999,4.501) A15(2.499,4.501) A16(2.999,4.501) A17(3.499,4.501) A18(3.999,4.501) A19(4.499,4.501) B1(-4.501,4.001) B2(-4.001,4.001) B3(-3.501,4.001) B4(-3.001,4.001) B5(-2.501,4.001) B6(-2.001,4.001) B7(-1.501,4.001) B8(-1.001,4.001) B9(-0.501,4.001) B10(-0.001,4.001) B11(0.499,4.001) B12(0.999,4.001) B13(1.499,4.001) B14(1.999,4.001) B15(2.499,4.001) B16(2.999,4.001) B17(3.499,4.001) B18(3.999,4.001) B19(4.499,4.001) C1(-4.501,3.501) C2(-4.001,3.501) C3(-3.501,3.501) C18(3.999,3.501) C19(4.499,3.501) D1(-4.501,3.001) D2(-4.001,3.001) D18(3.999,3.001) D19(4.499,3.001) E1(-4.501,2.501) E2(-4.001,2.501) E5(-2.501,2.501) E6(-2.001,2.501) E7(-1.501,2.501) E8(-1.001,2.501) E9(-0.501,2.501) E10(-0.001,2.501) E11(0.499,2.501) E12(0.999,2.501) E13(1.499,2.501) E14(1.999,2.501) E15(2.499,2.501) E18(3.999,2.501) E19(4.499,2.501) F1(-4.501,2.001) F2(-4.001,2.001) F5(-2.501,2.001) F15(2.499,2.001) F18(3.999,2.001) F19(4.499,2.001) G1(-4.501,1.501) G2(-4.001,1.501) G5(-2.501,1.501) G15(2.499,1.501) G18(3.999,1.501) G19(4.499,1.501) H1(-4.501,1.001) H2(-4.001,1.001) H5(-2.501,1.001) H15(2.499,1.001) H18(3.999,1.001) H19(4.499,1.001) J1(-4.501,0.501) J2(-4.001,0.501) J5(-2.501,0.501) J8(-1.001,0.501) J9(-0.501,0.501) J10(-0.001,0.501) J11(0.499,0.501) J12(0.999,0.501) J15(2.499,0.501) J18(3.999,0.501) J19(4.499,0.501) K1(-4.501,0.001) K2(-4.001,0.001) K5(-2.501,0.001) K8(-1.001,0.001) K9(-0.501,0.001) K10(-0.001,0.001) K11(0.499,0.001) K12(0.999,0.001) K15(2.499,0.001) K18(3.999,0.001) K19(4.499,0.001) L1(-4.501,-0.499) L2(-4.001,-0.499) L5(-2.501,-0.499) L8(-1.001,-0.499) L9(-0.501,-0.499) L10(-0.001,-0.499) L11(0.499,-0.499) L12(0.999,-0.499) L15(2.499,-0.499) L18(3.999,-0.499) L19(4.499,-0.499) M1(-4.501,-0.999) M2(-4.001,-0.999) M5(-2.501,-0.999) M15(2.499,-0.999) M18(3.999,-0.999) M19(4.499,-0.999) N1(-4.501,-1.499) N2(-4.001,-1.499) N5(-2.501,-1.499) N15(2.499,-1.499) N18(3.999,-1.499) N19(4.499,-1.499) P1(-4.501,-1.999) P2(-4.001,-1.999) P5(-2.501,-1.999) P15(2.499,-1.999) P18(3.999,-1.999) P19(4.499,-1.999) R1(-4.501,-2.499) R2(-4.001,-2.499) R5(-2.501,-2.499) R6(-2.001,-2.499) R7(-1.501,-2.499) R8(-1.001,-2.499) R9(-0.501,-2.499) R10(-0.001,-2.499) R11(0.499,-2.499) R12(0.999,-2.499) R13(1.499,-2.499) R14(1.999,-2.499) R15(2.499,-2.499) R18(3.999,-2.499) R19(4.499,-2.499) T1(-4.501,-2.999) T2(-4.001,-2.999) T18(3.999,-2.999) T19(4.499,-2.999) U1(-4.501,-3.499) U2(-4.001,-3.499) U3(-3.501,-3.499) U17(3.499,-3.499) U18(3.999,-3.499) U19(4.499,-3.499) V1(-4.501,-3.999) V2(-4.001,-3.999) V3(-3.501,-3.999) V4(-3.001,-3.999) V5(-2.501,-3.999) V6(-2.001,-3.999) V7(-1.501,-3.999) V8(-1.001,-3.999) V9(-0.501,-3.999) V10(-0.001,-3.999) V11(0.499,-3.999) V12(0.999,-3.999) V13(1.499,-3.999) V14(1.999,-3.999) V15(2.499,-3.999) V16(2.999,-3.999) V17(3.499,-3.999) V18(3.999,-3.999) V19(4.499,-3.999) W1(-4.501,-4.499) W2(-4.001,-4.499) W3(-3.501,-4.499) W4(-3.001,-4.499) W5(-2.501,-4.499) W6(-2.001,-4.499) W7(-1.501,-4.499) W8(-1.001,-4.499) W9(-0.501,-4.499) W10(-0.001,-4.499) W11(0.499,-4.499) W12(0.999,-4.499) W13(1.499,-4.499) W14(1.999,-4.499) W15(2.499,-4.499) W16(2.999,-4.499) W17(3.499,-4.499) W18(3.999,-4.499) W19(4.499,-4.499)
  silkscreen extent -5.76,-5.17 5.18,5.17, body extent -5.01,-5.02 5.02,5.02, height 0.91
CAPC0402-01 [mm] "Chip Capacitor, Body 1.0x0.5mm, Height 0.6mm, IPC Medium Density"
  rect 0.62x0.62 smd: 1(-0.45,0) 2(0.45,0)
  silkscreen extent -0.51,-0.51 0.51,0.51, body extent -0.55,-0.3 0.55,0.3, height 0.6
CAPC0805-01 [mil] "Chip Capacitor, Body 2.0x1.3mm, Height 0.90mm"
  rect 41.52x53.39 smd paste+0 mask+4: 1(-28.57,0) 2(28.57,0)
  silkscreen extent -30,-36 30,36, body extent -53,-32 53,32, height 10
CONN_77311-146-01LF_AMP_HDR_1X1_2.5MM_STRT_No3D [mil]
  rect 60x60 hole 38 mask+0: 1(0,0)
  silkscreen extent -55,-52 55,52
CONN_77311-146-02LF_AMP_HDR_1x2_2.5MM_STRT [mil]
  rect 60x60 hole 38 mask+0: 1(0,0)
  round 60 hole 40 mask+0: 2(-100,0)
  silkscreen extent -155,-67 70,52, body extent -150,-50 50,50, height 350
CONN_CUI_SJ-3523-SMT-TR [mm]
  rect 2.2x2.8 smd: 1(-1.1,-3.7) 3(0.9,3.7)
  rect 2.8x2.8 smd: 2(8.3,-3.7)
  round 1.7 hole 1.7 unplated: ""(0,0) ""(7,0)
  silkscreen extent -6,-4.37 11,3, body extent -6.04,-4.58 10.96,4.42, height 5
CONN_FPC_BM20B0834DS04V51_W/MODULE [mm] "OnSemi MIPI camera connector with module outline"
  rect 0.23x0.42 smd: 1(3.2,-1.09) 2(2.8,-1.09) 3(2.4,-1.09) 4(2,-1.09) 5(1.6,-1.09) 6(1.2,-1.09) 7(0.8,-1.09) 8(0.4,-1.09) 9(0,-1.09) 10(-0.4,-1.09) 11(-0.8,-1.09) 12(-1.2,-1.09) 13(-1.6,-1.09) 14(-2,-1.09) 15(-2.4,-1.09) 16(-2.8,-1.09) 17(-3.2,-1.09) 18(-3.2,1.09) 19(-2.8,1.09) 20(-2.4,1.09) 21(-2,1.09) 22(-1.6,1.09) 23(-1.2,1.09) 24(-0.8,1.09) 25(-0.4,1.09) 26(0,1.09) 27(0.4,1.09) 28(0.8,1.09) 29(1.2,1.09) 30(1.6,1.09) 31(2,1.09) 32(2.4,1.09) 33(2.8,1.09) 34(3.2,1.09)
  rect 0.3x0.75 smd: 35(-4.41,-0.925) 36(-4.41,0.925) 37(4.41,-0.925) 38(4.41,0.925)
  silkscreen extent -4.64,-1.9 4.64,1.91, body extent -4.83,-19.53 4.81,2.29, height 2.57
CONN_FPC_TOP-ENT_FRONT-SLIDE_0.50_8 [mm]
  rect 0.3x0.8 smd paste+0 mask+0.076: 1(-1.75,2.4) 2(-1.25,2.4) 3(-0.75,2.4) 4(-0.25,2.4) 5(0.25,2.4) 6(0.75,2.4) 7(1.25,2.4) 8(1.75,2.4)
  rect 1.3x3.05 smd paste+0 mask+0.076: 9(-3.65,0.475) 10(3.65,0.475)
  L1 region: -4.3,-0.2 -4.3,2 -5.4,2 -5.4,-0.2
  silkscreen extent -5.05,-2.5 5.05,3.43, body extent -5.02,-2.5 5.08,2.5, height 2
CONN_FPC_TOP-ENT_FRONT-SLIDE_0.50_20 [mm]
  rect 0.3x1.4 smd: 1(-4.75,0) 2(-4.25,0) 3(-3.75,0) 4(-3.25,0) 5(-2.75,0) 6(-2.25,0) 7(-1.75,0) 8(-1.25,0) 9(-0.75,0) 10(-0.25,0) 11(0.25,0) 12(0.75,0) 13(1.25,0) 14(1.75,0) 15(2.25,0) 16(2.75,0) 17(3.25,0) 18(3.75,0) 19(4.25,0) 20(4.75,0)
  rect 2.794x3.1 smd: 21(-6.674,-1.7) 22(6.674,-1.7)
  silkscreen extent -7.72,-4.55 7.72,1.27, body extent -7.75,-4.54 7.75,0.36, height 1.87
CONN_HDR_1X3_STRT_0.100 [mm] ".025 SQ Post Terminal Strip Assembly, 1x3 Pins, Vertical, 2.54mm Pitch, Male"
  rect 1.55x1.55 hole 1.02: 1(0,0)
  round 1.55 hole 1.02: 2(2.54,0) 3(5.08,0)
  silkscreen extent -1.46,-1.87 6.54,1.27, body extent -1.26,-1.26 6.36,1.28, height 8.89
CONN_HDR_1X3_STRT_0.100_no3D [mm] ".025 SQ Post Terminal Strip Assembly, 1x3 Pins, Vertical, 2.54mm Pitch, Male"
  rect 1.55x1.55 hole 1.02: 1(0,0)
  round 1.55 hole 1.02: 2(2.54,0) 3(5.08,0)
  silkscreen extent -1.81,-1.71 6.54,1.27
CONN_SAMTEC_TSW-106-07-G-S [mm]
  rect 1.37x1.37 hole 1.02: 1(-6.35,0)
  round 1.37 hole 1.02: 2(-3.81,0) 3(-1.27,0) 4(1.27,0) 5(3.81,0) 6(6.35,0)
  silkscreen extent -7.92,-1.95 7.82,1.4, body extent -7.73,-1.32 7.63,1.22, height 8.38
CONN_TSW-105-07-G-D_SAI [mil]
  rect 65x65 hole 45 mask+0: 1(0,0)
  round 65 hole 45 mask+0: 2(0,100) 3(100,0) 4(100,100) 5(200,0) 6(200,100) 7(300,0) 8(300,100) 9(400,0) 10(400,100)
  silkscreen extent -55,-93 455,155, body extent -47,-50 453,150, height 330
DFN6_3X3_ONS [mil]
  rect 32x16 smd paste+0 mask+4: 1(-55,37.4) 2(-55,0) 3(-55,-37.4) 4(55,-37.4) 5(55,0) 6(55,37.4)
  rect 63x98 smd paste+0 mask+0: 7(0,0)
  silkscreen extent -84,-64 64,64, body extent -59,-59 59,59, height 39
DHVQFN-14(2.5x3.0)_NXP [mm]
  rect 0.9x0.24 smd: 1(-1.55,-0.25) 7(1.55,-0.25) 8(1.55,0.25) 14(-1.55,0.25)
  rect 0.24x0.9 smd: 2(-1,-1.3) 3(-0.5,-1.3) 4(0,-1.3) 5(0.5,-1.3) 6(1,-1.3) 9(1,1.3) 10(0.5,1.3) 11(0,1.3) 12(-0.5,1.3) 13(-1,1.3)
  rect 1.4x0.9 smd: 15(0,0)
  silkscreen extent -2.38,-1.42 1.7,1.45, body extent -1.5,-1.25 1.5,1.25, height 1.1
FB_0402 [mm]
  rect 0.457x0.65 smd: 1(-0.425,0) 2(0.425,0)
  silkscreen extent -0.36,-0.46 0.35,0.46, body extent -0.7,-0.45 0.7,0.45, height 0.25
Hole_#4 [mil]
  round 230 hole 125: 1(0,0)
IC_ICM-42670-P [mm]
  rect 0.475x0.25 smd mask+0: 1(-1.162,0.75) 2(-1.162,0.25) 3(-1.162,-0.25) 4(-1.162,-0.75) 8(1.162,-0.75) 9(1.162,-0.25) 10(1.162,0.25) 11(1.162,0.75)
  rect 0.25x0.475 smd mask+0: 5(-0.5,-0.913) 6(0,-0.913) 7(0.5,-0.913) 12(0.5,0.913) 13(0,0.913) 14(-0.5,0.913)
  Keep-Out Layer region: 0.9,-0.65 -0.9,-0.65 -0.9,0.65 0.9,0.65
  Keep-Out Layer region: 0.9,-0.65 -0.9,-0.65 -0.9,0.65 0.9,0.65
  silkscreen extent -2.17,-1.25 1.5,1.25, body extent -1.5,-1.25 1.5,1.25, height 0.81
IND_IFSC_1515AH_VIS-M [mil]
  rect 87x160 smd paste+0: 1(-57.5,0) 2(57.5,0)
  silkscreen extent -112,-90 112,90, body extent -79,-79 79,79, height 71
INDC2520X120N [mm]
  rect 1.24x2.22 smd: 1(-1.09,0) 2(1.09,0)
  silkscreen extent -0.15,-1.1 0.15,1.1, body extent -1.25,-1 1.25,1, height 1.2
LED_0603-GRN_AK [mm] "SMT LED 0603 Green"
  rect 0.8x0.8 smd: A(-0.75,0) K(0.75,0)
  silkscreen extent -0.7,-0.6 0.97,0.71, body extent -0.8,-0.4 0.8,0.4, height 0.8
LED_SML-LX0404_LUM [mil]
  rect 18x18 smd paste+0: 1(-16.73,16.73) 2(16.73,16.73) 3(16.73,-16.73) 4(-16.73,-16.73)
  silkscreen extent -43,-32 32,32, body extent -19,-19 19,19, height 15
MIC_T5838 [mil]
  round 39 / inner round 0 / far side round 30 hole 39 unplated mask+4: 0(0,0)
  rect 20.55x28.54 smd: 1(-81.65,-32.99) 2(-49.29,-32.99) 6(-49.29,32.99) 7(-81.65,32.99)
  round 10 smd paste-2 mask+0: 3(29.54,-0.41)
  rect 13x13 smd: 4(29,-41) 5(29,41)
  L1 circle w12: c0,0 r30
  L1 lines w5: -25.68,-8.34 ccw(c0,0) -8.34,-25.68 ; -25.68,8.34 cw(c0,0) -8.34,25.68 ; 8.34,-25.68 ccw(c0,0) 25.68,-8.34 ; 8.34,25.68 cw(c0,0) 25.68,8.34
  silkscreen extent -103,-70 49,58, body extent -97,-52 41,52, height 38
MIC_T5848#1 [mm]
  round 0.991 / inner round 0 / far side round 0.762 hole 0.991 unplated mask+0.102: 0(0,0)
  rect 0.522x0.6 smd: 1(-2.072,-0.9) 2(-1.252,-0.9) 6(-1.252,0.9) 7(-2.072,0.9) 8(-2.072,0)
  round 0.254 smd paste-0.051 mask+0: 3(0.75,-0.01)
  rect 0.3x0.3 smd: 4(0.762,-1.041) 5(0.762,1.041)
  L1 lines w0.127: 0.652,0.212 ccw(c0,0) 0.212,0.652 ; 0.652,-0.212 cw(c0,0) 0.212,-0.652 ; -0.212,0.652 ccw(c0,0) -0.652,0.212 ; -0.212,-0.652 cw(c0,0) -0.652,-0.212
  L1 lines w0.305: 0.762,-0.022 ccw(c0,0) 0.026,0.762 ccw(c0,0) -0.762,0 ccw(c0,0) 0.762,-0.022
  silkscreen extent -2.64,-1.78 1.22,1.47, body extent -2.46,-1.32 1.04,1.32, height 1.04
MIC_T5848#2 [mm]
  round 0.991 / inner round 0 / far side round 0.762 hole 0.991 unplated mask+0.102: 0(0,0)
  rect 0.522x0.6 smd: 1(-2.072,-0.9) 2(-1.252,-0.9) 6(-1.252,0.9) 7(-2.072,0.9) 8(-2.072,0)
  round 0.254 smd paste-0.051 mask+0: 3(0.75,-0.01)
  rect 0.3x0.3 smd: 4(0.762,-1.041) 5(0.762,1.041)
  L1 lines w0.127: 0.652,0.212 ccw(c0,0) 0.212,0.652 ; 0.652,-0.212 cw(c0,0) 0.212,-0.652 ; -0.212,0.652 ccw(c0,0) -0.652,0.212 ; -0.212,-0.652 cw(c0,0) -0.652,-0.212
  L1 lines w0.305: 0.762,-0.01 cw(c0,0) -0.762,0 cw(c0,0) 0.762,-0.01
  silkscreen extent -2.64,-1.78 1.22,1.47, body extent -2.46,-1.32 1.04,1.32, height 1.04
MODULE_TELIT_WE310F5-I_ME310G1 [mm] "ME310G1 Telit Module"
  rect 0.6x0.6 smd mask+0.1: A3(-4.2,6.6) A5(-3,6.6) A7(-1.8,6.6) A9(-0.6,6.6) A11(0.6,6.6) A13(1.8,6.6) A15(3,6.6) A17(4.2,6.6) AA3(-4.2,-6.6) AA5(-3,-6.6) AA7(-1.8,-6.6) AA9(-0.6,-6.6) AA11(0.6,-6.6) AA13(1.8,-6.6) AA15(3,-6.6) AA17(4.2,-6.6) B2(-4.8,5.4) B4(-3.6,5.4) B6(-2.4,5.4) B8(-1.2,5.4) B10(0,5.4) B12(1.2,5.4) B14(2.4,5.4) B16(3.6,5.4) B18(4.8,5.4) C1(-6,4.8) C19(6,4.8) D2(-4.8,4.2) D7(-1.8,4.2) D9(-0.6,4.2) D11(0.6,4.2) D13(1.8,4.2) D18(4.8,4.2) E1(-6,3.6) E19(6,3.6) F2(-4.8,3) F8(-1.2,3) F12(1.2,3) F18(4.8,3) G1(-6,2.4) G4(-3.6,2.4) G16(3.6,2.4) G19(6,2.4) H2(-4.8,1.8) H6(-2.4,1.8) H14(2.4,1.8) H18(4.8,1.8) J1(-6,1.2) J4(-3.6,1.2) J16(3.6,1.2) J19(6,1.2) K2(-4.8,0.6) K18(4.8,0.6) L1(-6,0) L4(-3.6,0) L16(3.6,0) L19(6,0) M2(-4.8,-0.6) M18(4.8,-0.6) N1(-6,-1.2) N4(-3.6,-1.2) N16(3.6,-1.2) N19(6,-1.2) P2(-4.8,-1.8) P6(-2.4,-1.8) P14(2.4,-1.8) P18(4.8,-1.8) R1(-6,-2.4) R4(-3.6,-2.4) R16(3.6,-2.4) R19(6,-2.4) T2(-4.8,-3) T8(-1.2,-3) T12(1.2,-3) T18(4.8,-3) U1(-6,-3.6) U19(6,-3.6) V2(-4.8,-4.2) V7(-1.8,-4.2) V9(-0.6,-4.2) V11(0.6,-4.2) V13(1.8,-4.2) V18(4.8,-4.2) W1(-6,-4.8) W19(6,-4.8) Y2(-4.8,-5.4) Y4(-3.6,-5.4) Y6(-2.4,-5.4) Y8(-1.2,-5.4) Y10(0,-5.4) Y12(1.2,-5.4) Y14(2.4,-5.4) Y16(3.6,-5.4) Y18(4.8,-5.4)
  L1 keep-out region: -5.69,5.79 -5.881,5.828 -6.044,5.936 -6.152,6.099 -6.19,6.29 -6.19,6.29 -6.152,6.481 -6.044,6.644 -5.881,6.752 -5.69,6.79 -5.69,6.79 -5.499,6.752 -5.336,6.644 -5.228,6.481 -5.19,6.29 -5.19,6.29 -5.228,6.099 -5.336,5.936 -5.499,5.828 -5.69,5.79
  L1 keep-out region: -3.95,3.95 -3.95,3.25 -3.25,3.25 -3.25,3.95
  L1 keep-out region: 3.25,3.95 3.25,3.25 3.95,3.25 3.95,3.95
  L1 keep-out region: 3.25,-3.25 3.25,-3.95 3.95,-3.95 3.95,-3.25
  L1 keep-out region: -3.95,-3.25 -3.95,-3.95 -3.25,-3.95 -3.25,-3.25
  silkscreen extent -9.02,-7.49 7.87,11.2, body extent -7.53,-7.15 7.53,10.85, height 2.62
OSC_4p_2016_XRCGB38M400F2P00R0 [mm]
  rect 0.7x0.75 smd: 1(-0.5,0.675) 2(-0.5,-0.675) 3(0.5,-0.675) 4(0.5,0.675)
  silkscreen extent -0.91,-0.1 0.91,1.37, body extent -0.8,-1 0.8,1, height 0.7
OSC_4P_3225_1210_uChip_DSC1001DL5 [mm]
  rect 0.85x0.65 smd: 1(-0.775,0.825) 2(-0.775,-0.825) 3(0.775,-0.825) 4(0.775,0.825)
  silkscreen extent -1.6,-0.3 1.14,0.9, body extent -1.02,-1.24 1.02,1.24, height 0.94
PQFN50P250X300X88-14N [mm]
  rrect25% 0.59x0.35 smd: 1(-1.165,0.75) 2(-1.165,0.25) 3(-1.165,-0.25) 4(-1.165,-0.75) 8(1.165,-0.75) 9(1.165,-0.25) 10(1.165,0.25) 11(1.165,0.75)
  rrect25% 0.35x0.59 smd: 5(-0.5,-0.915) 6(0,-0.915) 7(0.5,-0.915) 12(0.5,0.915) 13(0,0.915) 14(-0.5,0.915)
  silkscreen extent -2.1,-1.25 1.5,1.25, body extent -1.5,-1.25 1.5,1.25, height 0.88
QFN32_5x5x1-0p5_INF-M [mil]
  rrect50% 36x10 smd paste+0: 1(-98.5,68.9) 2(-98.5,49.21) 3(-98.5,29.53) 4(-98.5,9.84) 5(-98.5,-9.84) 6(-98.5,-29.53) 7(-98.5,-49.21) 8(-98.5,-68.9) 17(98.5,-68.9) 18(98.5,-49.21) 19(98.5,-29.53) 20(98.5,-9.84) 21(98.5,9.84) 22(98.5,29.53) 23(98.5,49.21) 24(98.5,68.9)
  rrect50% 10x36 smd paste+0: 9(-68.9,-98.5) 10(-49.21,-98.5) 11(-29.53,-98.5) 12(-9.84,-98.5) 13(9.84,-98.5) 14(29.53,-98.5) 15(49.21,-98.5) 16(68.9,-98.5) 25(68.9,98.5) 26(49.21,98.5) 27(29.53,98.5) 28(9.84,98.5) 29(-9.84,98.5) 30(-29.53,98.5) 31(-49.21,98.5) 32(-68.9,98.5)
  rect 142x142 smd paste-70.5 mask+0: 33(0,0)
  silkscreen extent -140,-106 106,106, body extent -101,-101 101,101, height 39
QFN40P400X400X80-33N [mm]
  rect 0.8x0.2 smd: 1(-2,1.4) 2(-2,1) 3(-2,0.6) 4(-2,0.2) 5(-2,-0.2) 6(-2,-0.6) 7(-2,-1) 8(-2,-1.4) 17(2,-1.4) 18(2,-1) 19(2,-0.6) 20(2,-0.2) 21(2,0.2) 22(2,0.6) 23(2,1) 24(2,1.4)
  rect 0.2x0.8 smd: 9(-1.4,-2) 10(-1,-2) 11(-0.6,-2) 12(-0.2,-2) 13(0.2,-2) 14(0.6,-2) 15(1,-2) 16(1.4,-2) 25(1.4,2) 26(1,2) 27(0.6,2) 28(0.2,2) 29(-0.2,2) 30(-0.6,2) 31(-1,2) 32(-1.4,2)
  rect 2.75x2.75 smd: 33(0,0)
  silkscreen extent -2.5,1.9 -2.3,2.1, body extent -2.05,-2.05 2.05,2.05, height 0.8
RESC0402-01 [mm] "Chip Resistor, Body 1.0x0.5mm, IPC Medium Density"
  rect 0.55x0.65 smd: 1(-0.5,0) 2(0.5,0)
  silkscreen extent -0.51,-0.51 0.51,0.51, body extent -0.52,-0.27 0.53,0.28, height 0.4
SAMTEC_FTSH-110-01-X-DV-007-K [mm]
  rect 0.76x2.4 smd: 1(-5.715,-1.95) 2(-5.715,1.95) 3(-4.445,-1.95) 4(-4.445,1.95) 5(-3.175,-1.95) 6(-3.175,1.95) 8(-1.905,1.95) 9(-0.635,-1.95) 10(-0.635,1.95) 11(0.635,-1.95) 12(0.635,1.95) 13(1.905,-1.95) 14(1.905,1.95) 15(3.175,-1.95) 16(3.175,1.95) 17(4.445,-1.95) 18(4.445,1.95) 19(5.715,-1.95) 20(5.715,1.95)
  silkscreen extent -9.7,-4.02 9.6,3, body extent -6.31,-2.92 6.31,2.92, height 6.12
SC75_SSM_TOS-L [mm]
  rect 0.3x0.856 smd paste+0: 1(-0.5,-0.624) 2(0.5,-0.624) 3(0,0.624)
  silkscreen extent -0.93,-0.61 0.93,0.53, body extent -0.8,-0.8 0.8,0.8, height 0.75
SOD123F_NXP [mil]
  rect 54x30 smd paste+0 mask+4: 1(-58,0) 2(58,0)
  silkscreen extent -85,-39 58,39, body extent -71,-34 71,34, height 47
Solderbridge_Shorted#1 [mm]
  round 0.2 smd paste-10: 1(-0.338,0) 2(0.338,0)
  L1 region: 0.102,0.432 0.178,0.505 0.296,0.467 0.361,0.424 0.434,0.351 0.488,0.292 0.546,0.193 0.574,0.099 0.569,-0.122 0.544,-0.193 0.46,-0.33 0.376,-0.411 0.284,-0.469 0.183,-0.5 0.132,-0.483 0.102,-0.43
  L1 region: -0.102,-0.432 -0.178,-0.505 -0.296,-0.467 -0.361,-0.424 -0.434,-0.351 -0.488,-0.292 -0.546,-0.193 -0.574,-0.099 -0.569,0.122 -0.544,0.193 -0.46,0.33 -0.376,0.411 -0.284,0.469 -0.183,0.5 -0.132,0.483 -0.102,0.43
  L1 lines w0.152: 0.178,0.431 cw(c0.068,0) 0.178,-0.431 ; -0.178,0.431 ccw(c-0.068,0) -0.381,0.315 ccw(c-0.068,0) -0.512,0 ccw(c-0.068,0) -0.178,-0.431
  L1 lines w0.508: 0.338,0 -0.307,0 -0.338,0
Solderbridge_Shorted#2 [mm]
  round 0.2 smd paste-10: 1(-0.338,0) 2(0.338,0)
  L1 region: 0.102,0.432 0.178,0.505 0.296,0.467 0.361,0.424 0.434,0.351 0.488,0.292 0.546,0.193 0.574,0.099 0.569,-0.122 0.544,-0.193 0.46,-0.33 0.376,-0.411 0.284,-0.469 0.183,-0.5 0.132,-0.483 0.102,-0.43
  L1 region: -0.102,-0.432 -0.178,-0.505 -0.296,-0.467 -0.361,-0.424 -0.434,-0.351 -0.488,-0.292 -0.546,-0.193 -0.574,-0.099 -0.569,0.122 -0.544,0.193 -0.46,0.33 -0.376,0.411 -0.284,0.469 -0.183,0.5 -0.132,0.483 -0.102,0.43
  L1 lines w0.152: 0.178,-0.431 ccw(c0.068,0) 0.356,-0.339 ccw(c0.068,0) 0.432,-0.255 ccw(c0.068,0) 0.178,0.431 ; -0.178,-0.431 cw(c-0.068,0) -0.178,0.431
  L1 lines w0.203: 0.338,0 -0.338,0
